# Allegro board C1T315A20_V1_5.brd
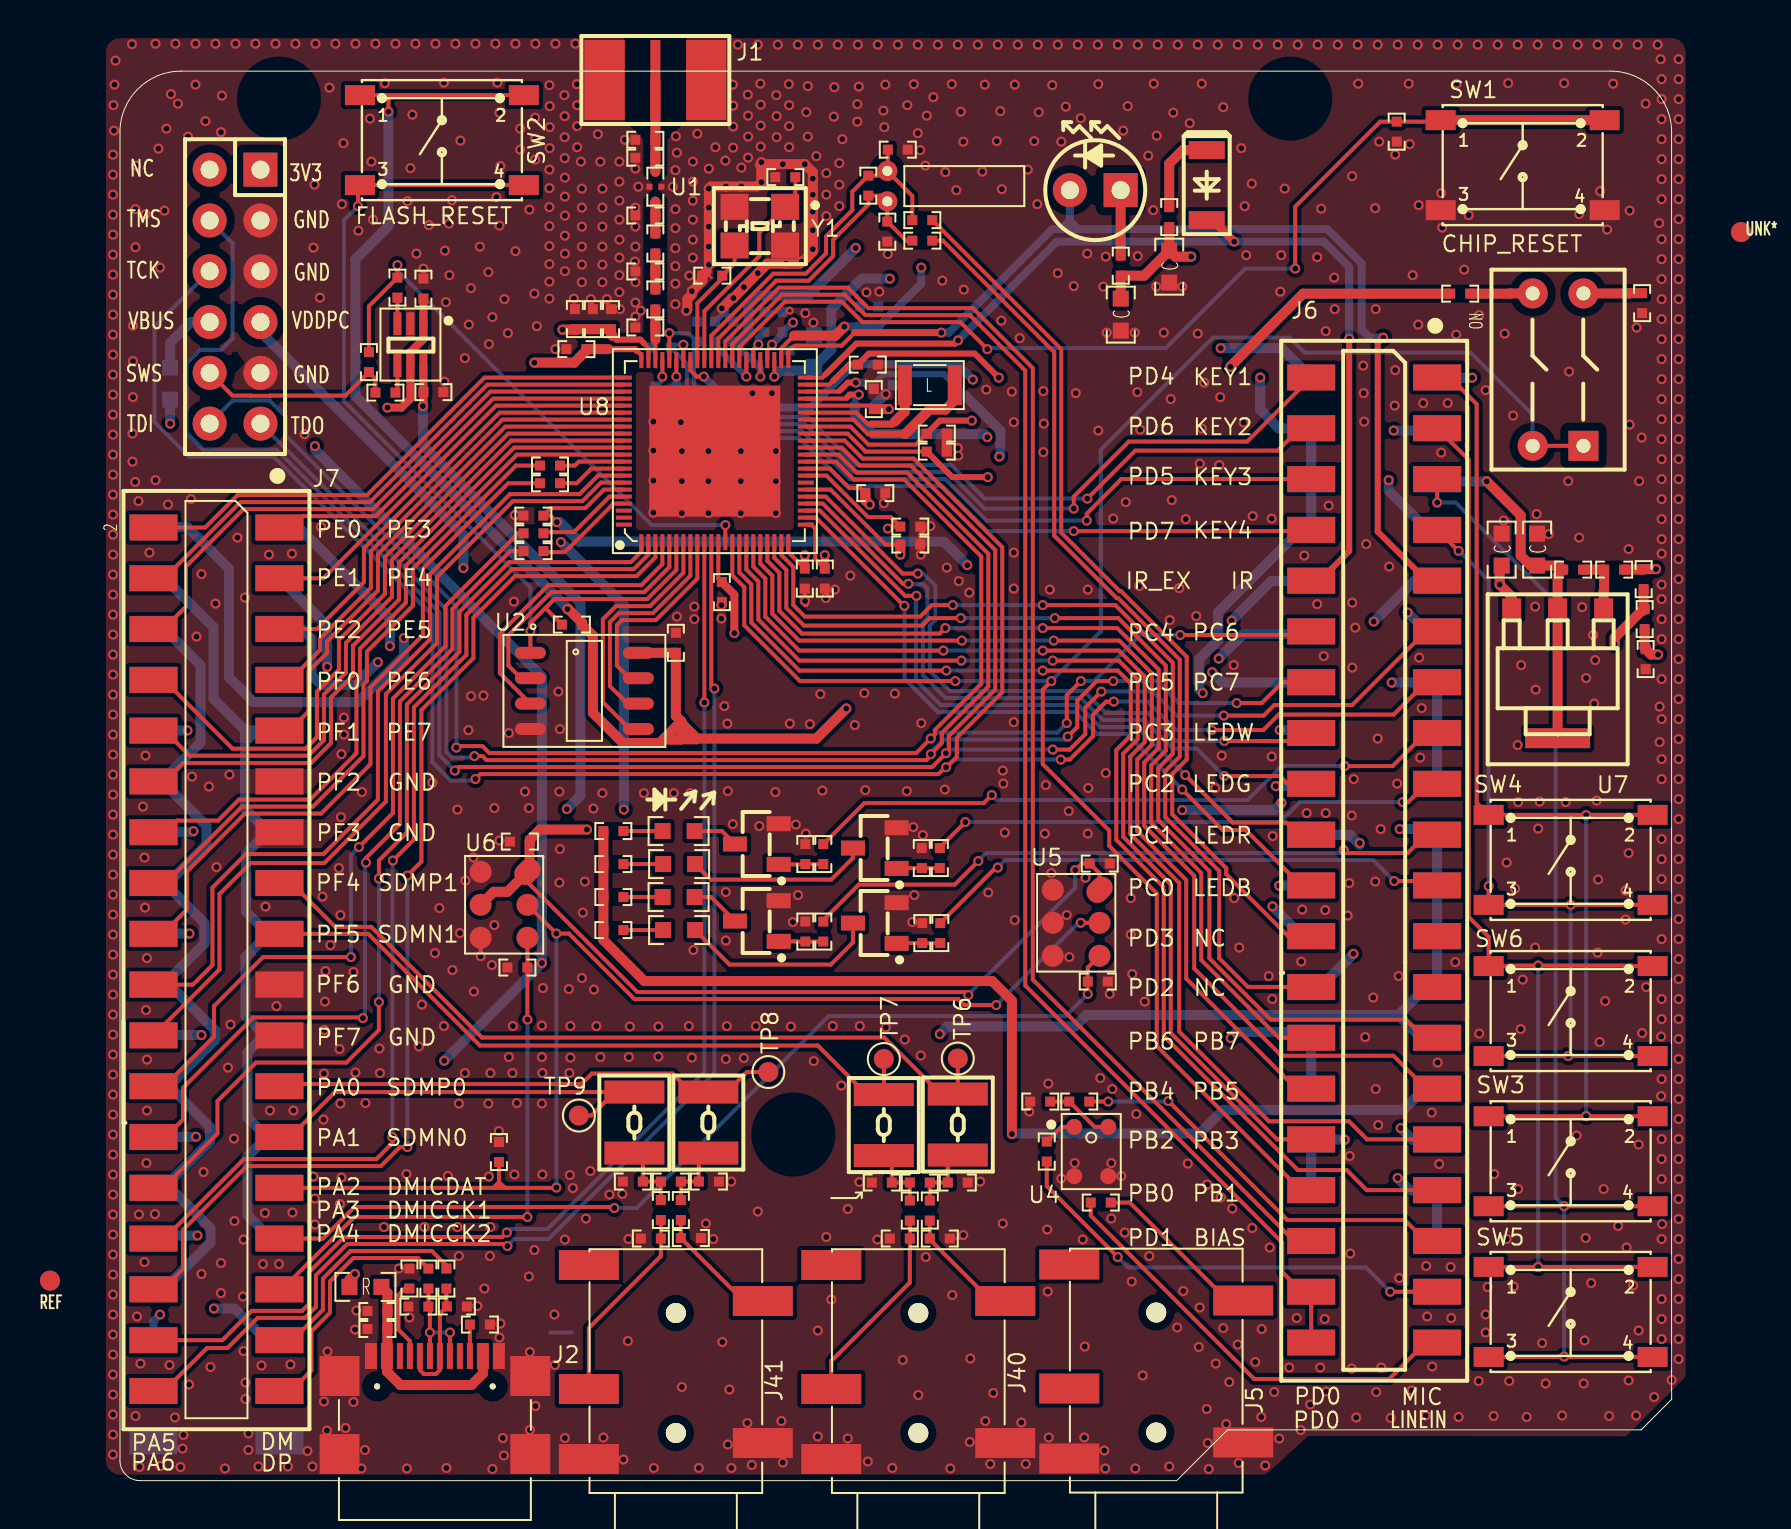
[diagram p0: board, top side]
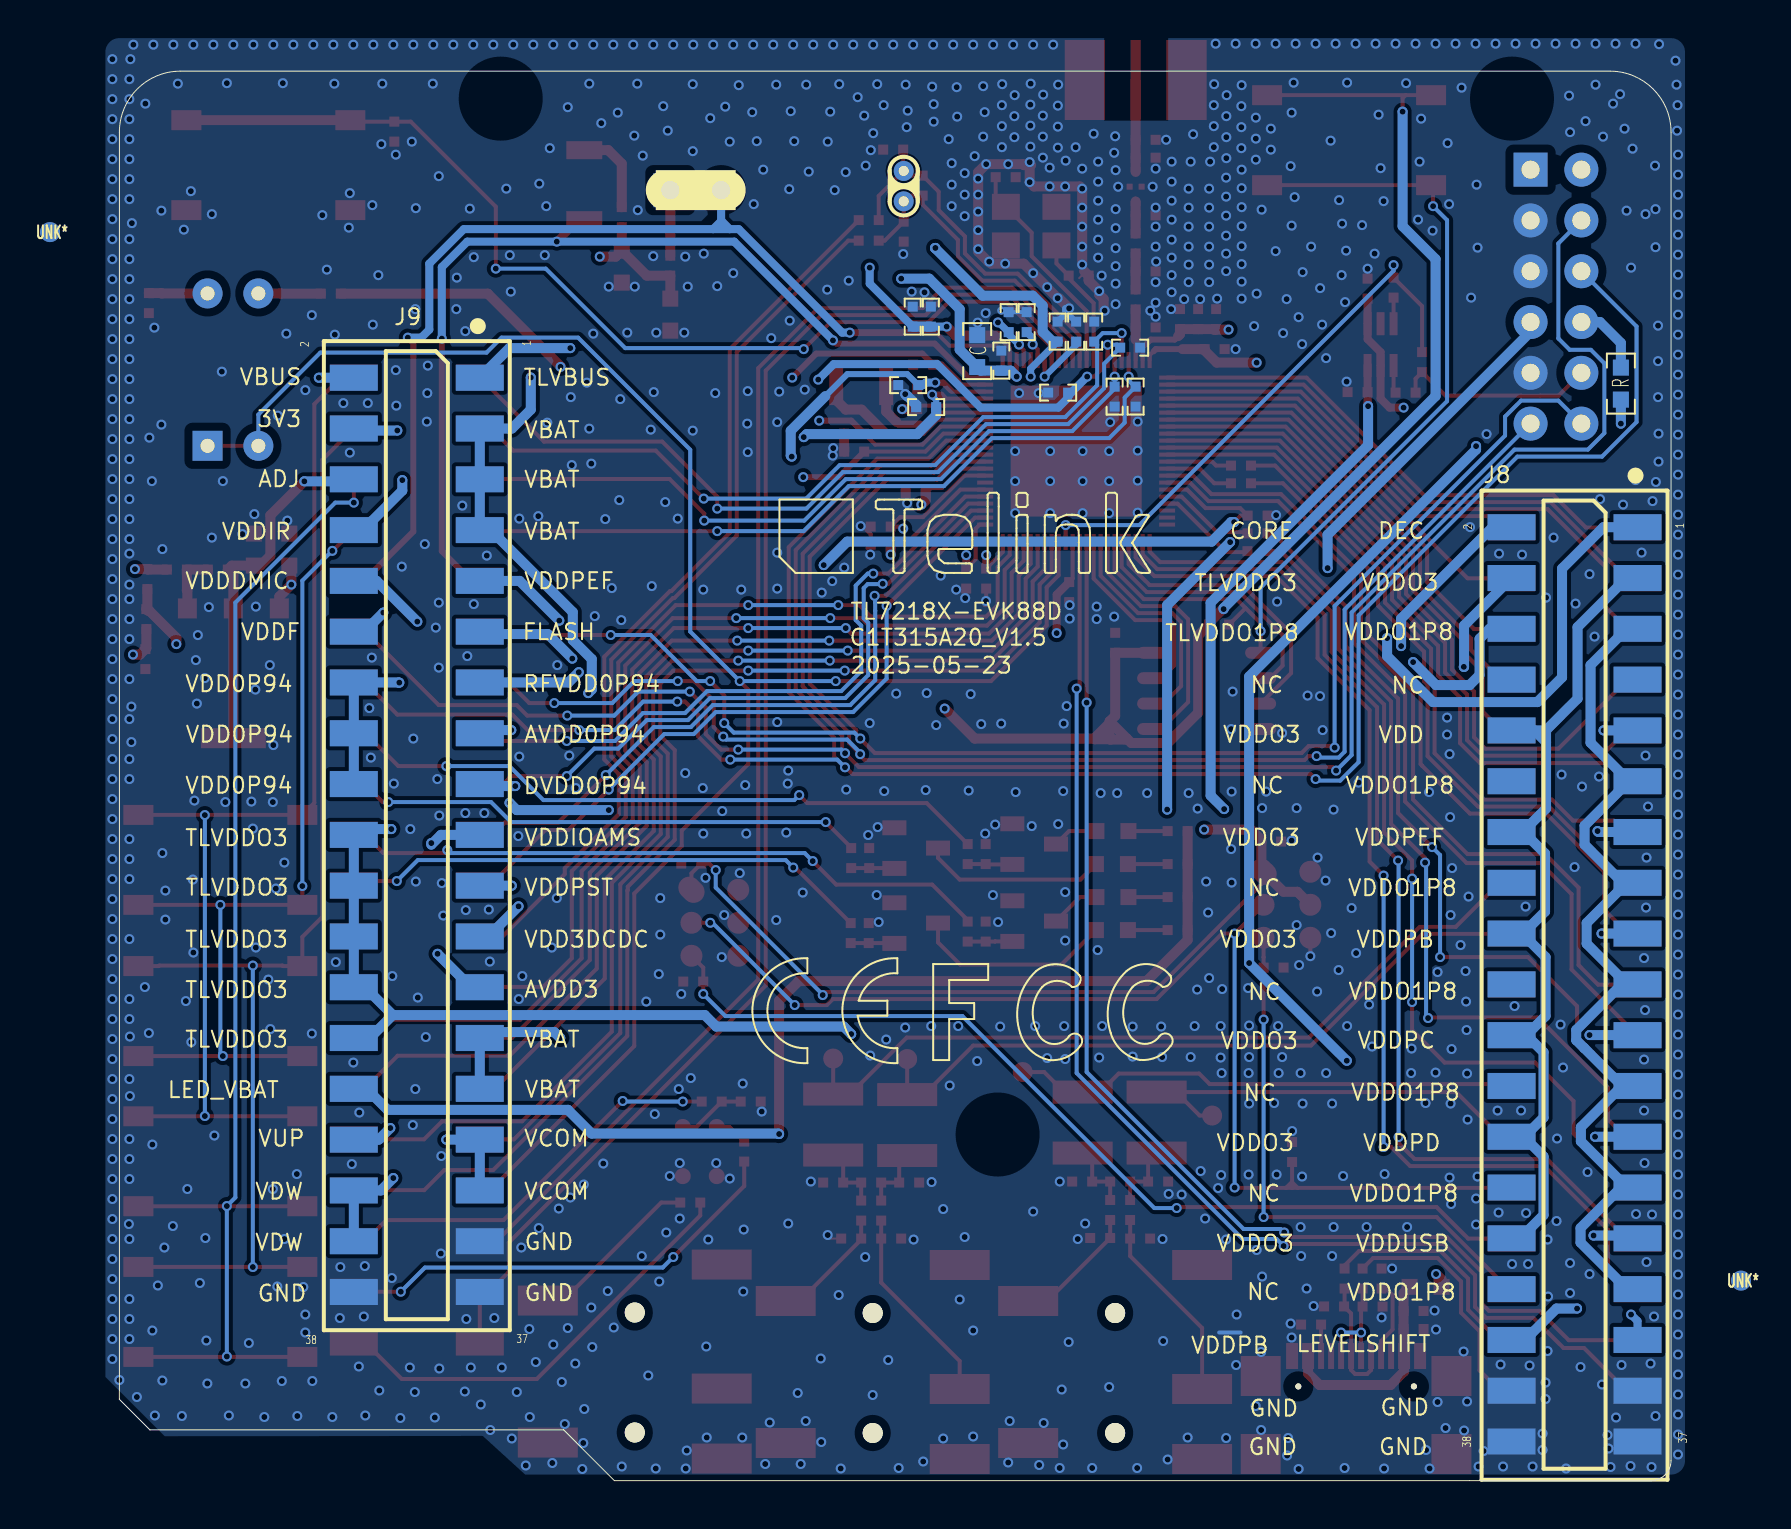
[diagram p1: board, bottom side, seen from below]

Outline 77.6 x 70.48 mm; copper layers: TOP, GND, POWER, BOTTOM. Coordinates in mm from the lower left corner of the outline.
Outline path: 0,67.43 arc(0.89,69.59) 3.05,70.48 74.55,70.48 arc(76.71,69.59) 77.6,67.43 77.6,4.06 76.08,2.54 55.39,2.54 52.85,0 1,0 arc(0.29,0.29) 0,1 0,67.43

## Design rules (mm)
constraint set DEFAULT: min track width 0.1

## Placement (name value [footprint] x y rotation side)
C1  10pF  [0402]  26.77 59.06 90 top
C2  0.5pF  [0402]  26.27 60.46 180 top
C3  3.3pF  [0402]  26.27 63.26 180 top
C4  0.1uF  [0402]  20.68 48.26 180 top
C5  NC  [0402]  29.62 60.26 0 top
C6  NC  [0402]  33.27 65.18 0 top
C7  0.1uF  [0402]  22.82 56.58 0 top
C8  0.1uF  [0402]  23.65 58.08 90 top
C9  4.7uF  [0402]  22.75 58.08 90 top
C10  0.1uF  [0402]  30.65 54.41 180 bottom
C11  1uF  [0402]  63.85 67.45 270 top
C12  0.1uF  [0402]  30.1 44.43 270 top
C13  1uF  [0402]  29.75 57.45 90 bottom
C14  1uF  [0402]  32.23 57.93 90 bottom
C15  1uF  [0402]  30.67 57.45 90 bottom
C17  10uF  [0603C]  34.7 56.48 90 bottom
C18  1uF  [0402]  33.12 57.93 90 bottom
C19  0.1uF  [0402]  34.25 45.1 270 top
C20  1uF  [0402]  37.92 58.2 90 bottom
C21  NC  [0402]  38.38 62.45 90 top
C22  NC  [0402]  38.9 66.56 180 top
C23  0.1uF  [0402]  35.25 45.1 270 top
C24  1uF  [0402]  37.4 55.8 0 top
C25  1uF  [0402]  39.52 46.8 0 top
C26  1uF  [0402]  40.85 51.45 0 top
C27  1uF  [0402]  37.25 53.68 0 bottom
C28  1uF  [0402]  38.15 54.78 0 bottom
C29  1uF  [0402]  39.52 47.7 0 top
C30  1uF  [0402]  37.7 54.08 90 top
C31  1uF  [0402]  37.77 49.38 0 top
C32  1uF  [0402]  40.85 52.35 0 top
C33  1uF  [0402]  27.8 41.89 90 top
C34  0.1uF  [0402]  15.68 54.43 0 top
C35  0.1uF  [0402]  15.18 59.6 90 top
C36  10uF  [0603C]  52.48 60.7 90 top
C37  10uF  [0603C]  50.05 58.3 90 top
C38  10nF  [0402]  46.35 16.45 270 top
C39  1uF  [0402]  46.02 18.95 180 top
C40  10nF  [0402]  49.05 13.9 180 top
C41  0.1uF  [0402]  49 30.86 0 top
C42  0.1uF  [0402]  20 31.95 180 top
C43  10uF  [0603C]  69.1 46.55 90 top
C44  10uF  [0603C]  70.88 46.55 90 top
C45  1.2pF  [0402]  26.27 66.15 180 top
C69  NC  [0402]  38.1 14.91 0 top
C73  220nF  [0402]  40 14.91 0 top
C75  22pF  [0402]  39 12.11 0 top
C76  22pF  [0402]  41 12.11 0 top
C115  NC  [0402]  41.9 14.91 0 top
C116  NC  [0402]  29.45 14.96 0 top
C117  NC  [0402]  25.65 14.96 0 top
C118  22pF  [0402]  26.55 12.11 0 top
C119  22pF  [0402]  28.55 12.13 0 top
C120  220nF  [0402]  27.55 14.96 0 top
C122  1nF  [0402]  18.95 16.43 90 top
C123  3.9pF  [0402]  27.05 56.65 180 bottom
C124  3.9pF  [0402]  27.83 54.2 270 bottom
C125  3.9pF  [0402]  28.85 57.45 90 bottom
C126  3.9pF  [0402]  26.78 54.2 270 bottom
C127  10uF  [0402]  12.88 8.48 0 top
D1  Red  [0603-LED]  27.94 29.18 0 top
D2  White  [0603-LED]  27.94 32.48 0 top
D3  Green  [0603-LED]  27.96 30.83 0 top
D4  Blue  [0603-LED]  27.96 27.53 0 top
D5  LED_IR  [LED_TH_2P54MM_2PIN]  48.77 64.53 0 top
D6  1N4148  [SOD80]  54.35 64.78 270 top
D7  TT0321  [0402]  26.27 57.66 0 top
D8  TT0321  [0402]  26.27 67.05 0 top
D9  ULC0142CDN  [0402]  24.56 58.08 270 top
D10  NC  [0402]  37.02 58.2 270 bottom
D11  ULC0342P10LV  [0402]  33.49 56.01 270 bottom
D12  ESDA05CP30  [0402]  12.88 7.58 0 top
D13  ULC0342P10LV  [0402]  14.93 8.7 180 top
D14  ULC0342P10LV  [0402]  16.85 8.71 0 top
J1  RFIN  [SMA-H]  26.77 70.04 90 top
J2  Type-C 16pin  [TYPE_C_CQ_105PWB]  15.75 5.23 0 top
J3  DIP_2X2  [DIPSWITCH_2P54_7P62_2X2]  71.92 55.55 0 top
J4  JTAG  [HDR254F-2X6X850]  7.03 52.85 90 top
J5  AIL1  [PJ-327]  51.83 -0.6 180 top
J6  HEADER 20x2  [SMD254M-2X20_RX1_30Y2_40]  62.72 28.5 90 top
J7  HEADER 18X2  [SMD254M-2X18_RX1_30Y2_40]  4.82 20.99 90 top
J8  HEADER 19x2  [HDR2X19-2R54-SM-M]  4.82 24.77 90 bottom
J9  HEADER 19x2  [HDR2X19-2R54-SM-M]  62.72 32.25 90 bottom
J40  PJ327  [PJ-327]  39.92 -0.62 180 top
J41  PJ327  [PJ-327]  27.8 -0.62 180 top
L1  2nH  [0402]  26.77 61.86 90 top
L2  6.8uH  [1008L]  40.5 54.78 0 top
L15  150uH  [INDM3025X25]  41.9 17.8 270 top
L16  150uH  [INDM3025X25]  38.2 17.78 270 top
L17  150uH  [INDM3025X25]  29.42 17.91 270 top
L18  150uH  [INDM3025X25]  25.73 17.91 270 top
Q1  C1815  [SOT-23]  31.85 27.98 90 top
Q2  C1815  [SOT-23]  37.75 27.88 90 top
Q3  C1815  [SOT-23]  31.85 31.83 90 top
Q4  C1815  [SOT-23]  37.75 31.63 90 top
R1  NC  [0402]  37.42 64.75 90 top
R3  4.7K  [0402]  22.6 42.8 180 top
R4  33  [0402]  15.43 10.11 90 top
R5  5.1K  [0402]  14.48 10.11 270 top
R6  33  [0402]  16.32 10.11 90 top
R7  1K  [0402]  67.03 59.35 180 top
R8  1M  [0402]  76.12 58.88 270 top
R9  2R  [0603R]  12.28 9.69 0 top
R10  5.1K  [0402]  18 7.8 180 top
R11  0R  [0402]  12.45 55.93 270 top
R12  1K  [0402]  24.68 29.18 0 top
R13  1K  [0402]  24.68 27.53 0 top
R14  1K  [0402]  24.68 32.48 0 top
R15  1K  [0402]  24.68 30.83 0 top
R16  1R  [0402]  50.05 60.76 90 top
R17  0R  [0402]  52.48 63.18 90 top
R18  2.2K  [0402]  47.98 18.95 180 top
R19  1K  [0402]  35.17 27.45 270 top
R20  1K  [0402]  41.02 27.38 270 top
R21  1K  [0402]  35.17 31.33 270 top
R22  1K  [0402]  41 31.13 270 top
R23  10K  [0402]  34.27 27.45 90 top
R24  10K  [0402]  40.12 27.38 90 top
R25  10K  [0402]  34.27 31.33 90 top
R26  10K  [0402]  40.1 31.13 90 top
R27  100K  [0402]  48.9 24.95 180 top
R28  100K  [0402]  19.88 25.66 0 top
R29  430R  [0402]  74.72 45.55 0 top
R30  1.15K  [0402]  76.2 45.08 270 top
R31  787R  [0402]  76.25 43.08 270 top
R32  464R  [0402]  76.3 41.08 270 top
R33  1K  [0402]  72.67 45.55 180 top
R34  0R  [0402]  40.12 62.01 180 top
R35  0R  [0402]  40.12 63.03 180 top
R36  NC  [0402]  13.88 59.66 270 top
R37  NC  [0402]  13.27 54.41 180 top
R38  2R  [0603R]  2.51 54.85 90 bottom
R40  240R  [0402R]  40.5 13.5 270 top
R41  240R  [0402R]  39.5 13.5 270 top
R42  240R  [0402R]  28.05 13.53 270 top
R43  240R  [0402R]  27.05 13.53 270 top
R44  0R  [0402R]  21.51 50.76 0 top
R45  0R  [0402R]  21.51 49.87 0 top
R46  0R  [0402R]  20.68 46.48 0 top
R47  0R  [0402R]  20.68 47.37 0 top
REF  -  [unnamed]  -3.5 10 0 top
SW1  SW4PIN_4.5x4.5  [SW_6X6_SMD]  70.15 65.78 0 top
SW2  FRST  [SW_6X6_SMD]  16.1 67.03 0 top
SW3  SW4PIN_4.5x4.5  [SW_6X6_SMD]  72.55 15.97 0 top
SW4  SW4PIN_4.5x4.5  [SW_6X6_SMD]  72.55 31.04 0 top
SW5  SW4PIN_4.5x4.5  [SW_6X6_SMD]  72.55 8.44 0 top
SW6  SW4PIN_4.5x4.5  [SW_6X6_SMD]  72.55 23.48 0 top
TP6  D5  [TP100]  41.9 21.11 0 top
TP7  D4  [TP100]  38.2 21.08 0 top
TP8  B1  [TP100]  32.42 20.43 270 top
TP9  B0  [TP100]  22.95 18.26 270 top
U1  1.2nH  [BANDPASS]  26.77 64.7 90 top
U2  P25Q16S  [W25X10_20_40BL]  23.23 39.49 270 top
U3  NC/TXS0101  [SC70-6]  14.52 56.8 180 top
U4  WMM7037AT2  [GA_BFA423_A83]  48.58 16.45 0 top
U5  WMM7047DTFN0  [DMIC_SPM0423HM4H-WB]  47.82 27.89 270 top
U6  WMM7047DTFN0  [DMIC_SPM0423HM4H-WB]  19.21 28.79 270 top
U7  LM1117-ADJ  [SOT-223]  71.9 40.12 180 top
U8  TL7218X  [QFN_9X9_88PIN_0P35_6P50X6P50]  29.75 51.48 90 top
UNK*  -  [unnamed]  81.07 62.43 0 top
UNK*#2  -  [unnamed]  81.07 62.43 180 bottom
UNK*#3  -  [unnamed]  -3.5 10 180 bottom
Y1  24MHz-6pF-+/-10ppm  [OSCCC250X320X110]  32 62.73 270 top
Y2  32.768KHz - 9pf - +/-20ppm  [OSC_2X6]  42.38 64.73 180 top

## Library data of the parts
C1-C3 C21 C22 C45 = C1608_NC
C4 C7-C15 C17-C20 C23-C33 C36-C40 C123-C127 = C1005X5R1C104K
C5 C6 C69 C115-C117 = C1005_NC
C34 C35 C44 = C1608X5R1C105M
C41 C42 C122 = C1005X5R1C104K_1
C43 = C1608X5R0J106M
C73 C120 = C1005X5R1C224M
C75 C76 C118 C119 = C1005C0G1H100D
D1-D4 = 0603D_Green
D5 = Led_Th_3mm_1: User Part Number: partnum; Tolerance: RichardLC
D6 = Diode_1N4148
D7 D13 D14 = ESD5B5_2.0ST1G
D8-D12 = ESD5B5_3.0ST1G
J1 = SMA_JACK_2
J2 = Type-C 16pin_0
J3 = HEADER 2X2_0: Tolerance: RichardLC; User Part Number: pn
J4 = HEADER 6X2: Tolerance: RichardLC; User Part Number: pn
J5 J40 J41 = PJ327_2
J6 = HEADER 20x2/M: Tolerance: RichardLC
J7 = HEADER 18X2: Tolerance: RichardLC
J8 J9 = HEADER 19x2: Tolerance: RichardLC
L1 = MLK1608_000R
L2 = IND_0: Tolerance: RichardLC; User Part Number: pn
L15-L18 = IND_150uH_3025
Q1-Q4 = NPN_C1815
R1 R11 = RS0603K102JT
R3 R7 R8 R18 R27 R28 R36 R37 = RS0402K104JT
R4-R6 R9 R10 = RS0402K330JT: room: USB
R12-R17 = RS0402K102JT
R19-R26 R34 R35 = RS0402K101JT
R29-R33 R38 = RS0603K104JT
R40-R43 = RS0402K330JT
R44 R46 R47 = R_7
R45 = R_6
SW1 SW3-SW6 = SW_6X6_SMD_0
SW2 = SW_6X6_SMD
TP6-TP9 = TestPad100
U1 = 4 HEADER_3
U2 = GD25LD40C_0: Tolerance: RichardLC
U3 = TXS0101
U4 = MULPS4CX-RM5_0
U5 U6 = LD1117/SO_0
U7 = XC62FP3302_0.3V_SOT-89
U8 = TL7218X-TLSR9258A-QFN88A: User Part Number: pn; Tolerance: RichardLC
Y1 = CRYSTAL4/SM_0: Tolerance: RichardLC
Y2 = OSC_2x6_2pin_16Mhz

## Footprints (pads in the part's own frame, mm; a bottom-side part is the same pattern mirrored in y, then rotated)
0402
  rect 0.5x0.5 smd: 1(-0.5,0) 2(0.5,0)
0402R
  rect 0.5x0.5 smd: 1(-0.5,0) 2(0.5,0)
0603-LED
  rect 0.8x0.8 smd: A(-0.8,0) C(0.8,0)
0603C
  rect 0.8x0.8 smd: 1(-0.8,0) 2(0.8,0)
0603R
  rect 0.8x0.8 smd: 1(-0.8,0) 2(0.8,0)
1008L
  rect 0.7x2 smd: 1(-1.25,0) 2(1.25,0)
BANDPASS
  rect 0.3x0.3 smd: 1(0,0.3) 3(0,-0.3)
  custom 0.125x0.125 smd: 2(0.74,0) 4(-0.74,0)
DIPSWITCH_2P54_7P62_2X2
  rect 1.5x1.5 hole 0.7: 1(1.27,-3.81)
  round 1.5 hole 0.7: 2(1.27,3.81) 3(-1.27,-3.81) 4(-1.27,3.81)
DMIC_SPM0423HM4H-WB
  round 1.1 smd: 1(-1.65,-1.17) 2(0,-1.17) 3(1.65,-1.17) 4(1.65,1.17) 5(0,1.17)
  oval 1.4x1.1 smd rot 135: 6(-1.65,1.17)
GA_BFA423_A83
  round 0.8 smd: 1(-0.85,1.23) 2(-0.85,-1.23) 3(0.85,-1.23) 4(0.85,1.23)
HDR2X19-2R54-SM-M
  rect 1.3x2.4 smd: 1(22.9,-3.15) 2(22.9,3.15) 3(20.36,-3.15) 4(20.36,3.15) 5(17.82,-3.15) 6(17.82,3.15) 7(15.28,-3.15) 8(15.28,3.15) 9(12.74,-3.15) 10(12.74,3.15) 11(10.2,-3.15) 12(10.2,3.15) 13(7.66,-3.15) 14(7.66,3.15) 15(5.12,-3.15) 16(5.12,3.15) 17(2.58,-3.15) 18(2.58,3.15) 19(0.04,-3.15) 20(0.04,3.15) 21(-2.5,-3.15) 22(-2.5,3.15) 23(-5.04,-3.15) 24(-5.04,3.15) 25(-7.58,-3.15) 26(-7.58,3.15) 27(-10.12,-3.15) 28(-10.12,3.15) 29(-12.66,-3.15) 30(-12.66,3.15) 31(-15.2,-3.15) 32(-15.2,3.15) 33(-17.74,-3.15) 34(-17.74,3.15) 35(-20.28,-3.15) 36(-20.28,3.15) 37(-22.82,-3.15) 38(-22.82,3.15)
HDR254F-2X6X850
  rect 1.7x1.7 hole 0.9: 1(12.7,0)
  round 1.7 hole 0.9: 2(12.7,2.54) 3(10.16,0) 4(10.16,2.54) 5(7.62,0) 6(7.62,2.54) 7(5.08,0) 8(5.08,2.54) 9(2.54,0) 10(2.54,2.54) 11(0,0) 12(0,2.54)
INDM3025X25
  rect 1.15x3 smd: 1(-1.525,0) 2(1.525,0)
LED_TH_2P54MM_2PIN
  rect 1.7x1.7 hole 0.9: A(1.27,0)
  round 1.7 hole 0.9: C(-1.27,0)
OSC_2X6
  round 1 hole 0.5: 1(4,0.76) 2(4,-0.76)
OSCCC250X320X110
  rect 1.3x1.4 smd: 1(-0.965,1.265) 2(-0.965,-1.265) 3(0.965,-1.265) 4(0.965,1.265)
PJ-327
  round 1 hole 1 unplated: (0,-3) (0,-9)
  rect 3x1.5 smd: 1(-4.35,-2.5) 2(4.35,-5.2) 3(-4.35,-9.6) 4(4.35,-11.4) 5(4.35,-1.7)
QFN_9X9_88PIN_0P35_6P50X6P50
  rect 0.8x0.2 smd: 1(-4.55,3.675) 2(-4.55,3.325) 3(-4.55,2.975) 4(-4.55,2.625) 5(-4.55,2.275) 6(-4.55,1.925) 7(-4.55,1.575) 8(-4.55,1.225) 9(-4.55,0.875) 10(-4.55,0.525) 11(-4.55,0.175) 12(-4.55,-0.175) 13(-4.55,-0.525) 14(-4.55,-0.875) 15(-4.55,-1.225) 16(-4.55,-1.575) 17(-4.55,-1.925) 18(-4.55,-2.275) 19(-4.55,-2.625) 20(-4.55,-2.975) 21(-4.55,-3.325) 22(-4.55,-3.675) 45(4.55,-3.675) 46(4.55,-3.325) 47(4.55,-2.975) 48(4.55,-2.625) 49(4.55,-2.275) 50(4.55,-1.925) 51(4.55,-1.575) 52(4.55,-1.225) 53(4.55,-0.875) 54(4.55,-0.525) 55(4.55,-0.175) 56(4.55,0.175) 57(4.55,0.525) 58(4.55,0.875) 59(4.55,1.225) 60(4.55,1.575) 61(4.55,1.925) 62(4.55,2.275) 63(4.55,2.625) 64(4.55,2.975) 65(4.55,3.325) 66(4.55,3.675)
  rect 0.2x0.8 smd: 23(-3.675,-4.55) 24(-3.325,-4.55) 25(-2.975,-4.55) 26(-2.625,-4.55) 27(-2.275,-4.55) 28(-1.925,-4.55) 29(-1.575,-4.55) 30(-1.225,-4.55) 31(-0.875,-4.55) 32(-0.525,-4.55) 33(-0.175,-4.55) 34(0.175,-4.55) 35(0.525,-4.55) 36(0.875,-4.55) 37(1.225,-4.55) 38(1.575,-4.55) 39(1.925,-4.55) 40(2.275,-4.55) 41(2.625,-4.55) 42(2.975,-4.55) 43(3.325,-4.55) 44(3.675,-4.55) 67(3.675,4.55) 68(3.325,4.55) 69(2.975,4.55) 70(2.625,4.55) 71(2.275,4.55) 72(1.925,4.55) 73(1.575,4.55) 74(1.225,4.55) 75(0.875,4.55) 76(0.525,4.55) 77(0.175,4.55) 78(-0.175,4.55) 79(-0.525,4.55) 80(-0.875,4.55) 81(-1.225,4.55) 82(-1.575,4.55) 83(-1.925,4.55) 84(-2.275,4.55) 85(-2.625,4.55) 86(-2.975,4.55) 87(-3.325,4.55) 88(-3.675,4.55)
  rect 6.55x6.55 smd: 89(0,0)
SC70-6
  rect 0.4x1.15 smd: 1(-0.65,-1.045) 2(0,-1.045) 3(0.65,-1.045) 4(0.65,1.045) 5(0,1.045) 6(-0.65,1.045)
SMA-H
  rect 4x0.5 smd: 1(0,0)
  rect 4x2 smd: 2(0,-2.54) 3(0,2.54) 4(0,-2.54) 5(0,2.54)
SMD254M-2X18_RX1_30Y2_40
  rect 1.3x2.4 smd: 1(26.67,-3.15) 2(26.67,3.15) 3(24.13,-3.15) 4(24.13,3.15) 5(21.59,-3.15) 6(21.59,3.15) 7(19.05,-3.15) 8(19.05,3.15) 9(16.51,-3.15) 10(16.51,3.15) 11(13.97,-3.15) 12(13.97,3.15) 13(11.43,-3.15) 14(11.43,3.15) 15(8.89,-3.15) 16(8.89,3.15) 17(6.35,-3.15) 18(6.35,3.15) 19(3.81,-3.15) 20(3.81,3.15) 21(1.27,-3.15) 22(1.27,3.15) 23(-1.27,-3.15) 24(-1.27,3.15) 25(-3.81,-3.15) 26(-3.81,3.15) 27(-6.35,-3.15) 28(-6.35,3.15) 29(-8.89,-3.15) 30(-8.89,3.15) 31(-11.43,-3.15) 32(-11.43,3.15) 33(-13.97,-3.15) 34(-13.97,3.15) 35(-16.51,-3.15) 36(-16.51,3.15)
SMD254M-2X20_RX1_30Y2_40
  rect 1.3x2.4 smd: 1(26.67,-3.15) 2(26.67,3.15) 3(24.13,-3.15) 4(24.13,3.15) 5(21.59,-3.15) 6(21.59,3.15) 7(19.05,-3.15) 8(19.05,3.15) 9(16.51,-3.15) 10(16.51,3.15) 11(13.97,-3.15) 12(13.97,3.15) 13(11.43,-3.15) 14(11.43,3.15) 15(8.89,-3.15) 16(8.89,3.15) 17(6.35,-3.15) 18(6.35,3.15) 19(3.81,-3.15) 20(3.81,3.15) 21(1.27,-3.15) 22(1.27,3.15) 23(-1.27,-3.15) 24(-1.27,3.15) 25(-3.81,-3.15) 26(-3.81,3.15) 27(-6.35,-3.15) 28(-6.35,3.15) 29(-8.89,-3.15) 30(-8.89,3.15) 31(-11.43,-3.15) 32(-11.43,3.15) 33(-13.97,-3.15) 34(-13.97,3.15) 35(-16.51,-3.15) 36(-16.51,3.15) 37(-19.05,-3.15) 38(-19.05,3.15) 39(-21.59,-3.15) 40(-21.59,3.15)
SOD80
  rect 0.9x1.8 smd: A(-1.75,0) C(1.75,0)
SOT-23
  rect 0.75x1.2 smd: 1(-1.016,-1.092) 2(1.016,-1.092) 3(0,1.092)
SOT-223
  rect 0.95x1 smd: 1(-2.3,-3.495) 2(0,-3.495) 3(2.3,-3.495)
  rect 3.25x1 smd: 4(0,2.995)
SW_6X6_SMD
  rect 1.5x1 smd: 1(-4.1,2.25) 2(4.1,2.25) 3(-4.1,-2.25) 4(4.1,-2.25)
TP100
  round 1 smd: 1(0,0)
TYPE_C_CQ_105PWB
  round 0.3 hole 0.7 unplated: (-2.89,-0.52) (2.89,-0.52)
  rect 2x2 smd: 13(-4.77,0) 14(4.77,0) 15(-4.77,-3.9) 16(4.77,-3.9)
  rect 0.6x1.3 smd: A1B12(-3.2,1) A4B9(-2.4,1) B1A12(3.2,1) B4A9(2.4,1)
  rect 0.3x1.3 smd: A5(-1.25,1) A6(-0.25,1) A7(0.25,1) A8(1.25,1) B5(1.75,1) B6(0.75,1) B7(-0.75,1) B8(-1.75,1)
unnamed
  round 1 smd: 1(0,0)
W25X10_20_40BL
  oval 0.6x1.55 smd: 1(-1.905,-2.7) 2(-0.635,-2.7) 3(0.635,-2.7) 4(1.905,-2.7) 5(1.905,2.7) 6(0.635,2.7) 7(-0.635,2.7) 8(-1.905,2.7)

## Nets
GND: C2.2 C3.2 C4.2 C5.1 C6.1 C7.1 C8.2 C9.2 C10.1 C11.2 C12.2 C13.2 C14.2 C15.2 C17.2 C18.2 C19.2 C20.2 C21.1 C22.1 C23.2 C24.2 C25.2 C26.2 C27.2 C28.2 C29.2 C30.2 C31.2 C32.2 C33.2 C34.2 C35.2 C36.1 C37.1 C39.2 C41.2 C42.2 C43.2 C44.2 C45.2 C69.1 C75.1 C76.2 C115.2 C116.2 C117.1 C118.1 C119.2 C122.2 C123.2 C124.2 C125.2 C126.2 C127.1 D7.1 D8.1 D9.1 D10.1 D11.1 D12.1 D13.2 D14.2 J1.2 J1.3 J1.4 J1.5 J2.13 J2.14 J2.15 J2.16 J2.A1B12 J2.B1A12 J4.3 J4.5 J4.9 J5.1 J5.5 J7.11 J7.13 J7.19 J7.21 J8.35 J8.36 J8.37 J8.38 J9.35 J9.37 J9.38 J40.1 J40.5 J41.1 J41.5 Q1.2(E) Q2.2(E) Q3.2(E) Q4.2(E) R5.1 R8.2 R10.1 R23.2 R24.2 R25.2 R26.2 R27.1 R28.1 R32.2 SW1.3 SW1.4 U1.1 U1.3 U2.4 U3.2 U4.2 U4.3 U5.1 U5.2(SE) U5.3 U6.1 U6.3 U8.89 Y1.2 Y1.4
VBAT_ADJ: C44.1 J9.6 R33.2 U7.2 U7.4(VOUT#4)
VBUS: C43.1 J9.2 R9.1 R38.1 U7.3
VDDO1P8: J8.5 J8.11 J8.15 J8.19 J8.23 J8.27 J8.31
VDDO3: J8.3 J8.10 J8.14 J8.18 J8.22 J8.26 J8.30
AIN_LINEIN: C40.2 J6.39
AIN_MIC: C38.2 J6.37
BEVK_SWS: J4.10 R11.2 R37.2
DM: D14.1 J2.A7 J2.B7 R6.1
DMICCK1: J7.29 R27.2 U5.4
DMICCK2: J7.31 R28.2 U6.4
DMICDAT: C122.1 J7.27 U5.5 U6.5
DP: D13.1 J2.A6 J2.B6 R4.1
EXT_3V3: C34.1 J4.1 J9.4 U3.6(VCCB)
LED_B: J6.21 R20.1
LED_G: J6.17 R22.1
LED_R: J6.19 R19.1
LED_VBAT: J9.30 R12.1 R13.1 R14.1 R15.1
LED_W: J6.15 R21.1
LEVEL_SHIFT: C35.1 J8.33 U3.1 U3.5
MICBIAS: J6.35 R18.1
TL_ANT: C1.1 D7.2 U8.64
TL_AVDD0P94: C28.1 J9.15 U8.42
TL_AVDD3: C15.1 J9.25 U8.49
TL_DM: J7.33 R6.2
TL_DP: J7.35 R4.2
TL_DVDD0P94: C27.1 J9.17 U8.41
TL_FLASH: C33.1 J9.11 R3.1 SW2.1 SW2.2 U2.8
TL_IR: D5.C(CATHODE) J6.9 U8.45
TL_IR_EX_DIOD: D6.C J6.10 U8.44
TL_KEY1: J6.1 SW3.1 SW3.2 SW4.1 SW4.2
TL_KEY2: J6.3 SW5.1 SW5.2 SW6.1 SW6.2
TL_KEY3: J6.5 SW3.3 SW3.4 SW5.3 SW5.4
TL_KEY4: J6.7 SW4.3 SW4.4 SW6.3 SW6.4
TL_PA0: J7.24 R47.1
TL_PA0_SDMP0: J7.23 L17.1 TP8.1(TP)
TL_PA1: J7.26 R46.1
TL_PA1_SDMN0: J7.25 L18.1 TP9.1(TP)
TL_PA2: J7.28 U8.1
TL_PA3: J7.30 U8.2
TL_PA4: J7.32 U8.3
TL_PA5_DM: J7.34 U8.10
TL_PA6_DP: J7.36 U8.11
TL_PA7_SWS: R11.1 R36.1 U8.13
TL_PB0: J3.1 J3.3 J6.34 U8.14
TL_PB1: J6.33 U8.15
TL_PB2: J6.32 U8.16
TL_PB3: J6.31 U8.17
TL_PB4: J6.30 U8.18
TL_PB5: J6.29 U8.19
TL_PB6: J6.28 U8.20
TL_PB7: J6.27 U8.21
TL_PC0: J6.22 U8.24
TL_PC1: J6.20 U8.25
TL_PC2: J6.18 U8.26
TL_PC3: J6.16 U8.27
TL_PC4_TDI: J4.12 J6.12 U8.32
TL_PC5_TDO: J4.11 J6.14 U8.33
TL_PC6_TMS: J4.4 J6.11 U8.34
TL_PC7_TCK: J4.6 J6.13 U8.35
TL_PD0_AMIC: J6.38 J6.40 U8.53
TL_PD1_MICBIAS: J6.36 U8.54
TL_PD2_32K: C21.2 R1.1 R34.2 U8.55 Y2.1
TL_PD2_NC_32K: J6.26 R34.1
TL_PD3_32K: C22.2 R1.2 R35.2 U8.56 Y2.2
TL_PD3_NC_32K: J6.24 R35.1
TL_PD4: C123.1 J6.2 U8.60
TL_PD5: C124.1 J6.6 U8.61
TL_PD6: C125.1 J6.4 U8.62
TL_PD7: C126.1 J6.8 U8.63
TL_PE0: J7.2 U8.67
TL_PE1: J7.4 U8.68
TL_PE2: J7.6 U8.69
TL_PE3: J7.1 U8.70
TL_PE4: J7.3 U8.71
TL_PE5: J7.5 U8.72
TL_PE6: J7.7 U8.73
TL_PE7: J7.9 U8.74
TL_PF0: J7.8 U8.75
TL_PF1: J7.10 U8.76
TL_PF2: J7.12 U8.77
TL_PF3: J7.14 U8.78
TL_PF4: J7.16 R44.1
TL_PF4_SDMP1: J7.15 L15.1 TP6.1(TP)
TL_PF5: J7.18 R45.1
TL_PF5_SDMN1: J7.17 L16.1 TP7.1(TP)
TL_PF6: J7.20 U8.81
TL_PF7: J7.22 U8.82
TL_PG0_MOSI: U2.5 U8.7
TL_PG1_MCLK: U2.6 U8.8
TL_PG2_MSIO3: U2.7 U8.9
TL_PG3_MSCN: R3.2 SW2.3 SW2.4 U2.1 U8.6
TL_PG4_MISO: U2.2 U8.5
TL_PG5_MSIO2: U2.3(W\P\/IO2) U8.4
TL_RFVDD_0P94: C8.1 C9.1 D9.2 J9.13 U8.65
TL_VBAT: C17.1 D11.2 J9.3 J9.5 J9.7 J9.27 J9.29 U8.47
TL_VBUS: C20.1 D10.2 J9.1 U8.46
TL_VDD: C7.2 J8.9 U8.66
TL_VDD0P94: C30.1 J9.14 J9.16 J9.18 U8.40
TL_VDD3DCDC: C32.1 J9.23 U8.37
TL_VDD_DMIC: C41.1 C42.1 J9.10 U5.6 U6.2(SE) U6.6
TL_VDD_F: C24.1 J9.12 U8.43
TL_VDD_IR: C36.2 C37.2 J9.8 R16.1 R17.1
TL_VDDCORE: C29.1 J8.2 U8.30
TL_VDDDEC: C31.1 J8.1 U8.31
TL_VDDIO_AMS: C14.1 J9.19 U8.50
TL_VDDIO_PB: C19.1 J8.17 J8.34 U8.22
TL_VDDIO_PC: C23.1 J4.7 J8.21 U8.23
TL_VDDIO_PD: C10.2 J8.25 U8.59
TL_VDDIO_PEF: C4.1 J8.13 J9.9 U8.83
TL_VDDIO_USB: C12.1 J8.29 U8.12
TL_VDDO1P8: C25.1 J8.6 U8.28
TL_VDDO3: C18.1 J8.4 J9.20 J9.22 J9.24 J9.26 J9.28 R7.2 U8.48
TL_VDDPST: C26.1 J9.21 U8.36
TL_XC1: C5.2 U8.58 Y1.3
TL_XC2: C6.2 U8.57(XC2) Y1.1
USB_VBUS: C127.2 D12.2 J2.A4B9 J2.B4A9(VBUS#B4A9) R9.2
VCOM: J9.31 J9.33 R30.2 R31.1
VDW: J9.34 J9.36 R31.2 R32.1
VUP: J9.32 R29.2 R30.1
N20028206: R29.1 R33.1 U7.1
N20230476: Q1.1 R19.2 R23.1
N20230490: Q2.1 R20.2 R24.1
N20230526: Q3.1 R21.2 R25.1
N20230570: Q4.1 R22.2 R26.1
N20230742: D1.A R12.2
N20230744: D1.C(CATHODE) Q1.3
N20230746: D4.A R13.2
N20230748: D4.C(CATHODE) Q2.3
N20230750: D2.A R14.2
N20230752: D2.C(CATHODE) Q3.3
N20230754: D3.A R15.2
N20230756: D3.C(CATHODE) Q4.3
N20248227: C39.1 R18.2 U4.4(VDD)
N20254983: C38.1 U4.1
N20255175: C40.1 J5.3
N20271178: D5.A R16.2
N20271193: D6.A R17.2
N20286198: R45.2 U8.80
N20286201: R44.2 U8.79
N20286912: C11.1 SW1.1 SW1.2 U8.52
N20286959: C13.1 U8.51
N20290975: L2.2 U8.38
N20290977: L2.1 U8.39
N20305837: J2.A5 R5.2
N20305839: J2.B5 R10.2
N20310970: C1.2 C2.1 L1.1
N20310976: C3.1 L1.2 U1.4
N20348750: J4.8 R38.2
N20353968: C69.2 C73.1 L16.2 R41.1
N20353978: C75.2 J40.2 R41.2
N20354017: C73.2 C115.1 L15.2 R40.1
N20354025: C76.1 J40.3 R40.2
N20354127: C117.2 C120.1 L18.2 R43.1
N20354137: C118.2 J41.2 R43.2
N20354176: C116.1 C120.2 L17.2 R42.1
N20354184: C119.1 J41.3 R42.2
N20364573: C45.1 D8.2 J1.1 U1.2
N20368232: R36.2 U3.3
N20378065: R47.2 U8.84
N20378070: R46.2 U8.85
N202243015: R37.1 U3.4
N202309440: J3.2 R8.1
N202309690: J3.4 R7.1

Pads without a net: J2 A8 B8; J4 2; J5 2 4; J6 23 25; J8 7 8 12 16 20 24 28 32; J40 4; J41 4; REF 1; U8 29 86 87 88; UNK* 1; UNK*#2 1; UNK*#3 1

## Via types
v1: diameter 0.5, hole 0.3, TOP to BOTTOM, 1355 vias
v2: diameter 0.4, hole 0.2, TOP to BOTTOM, 1 via

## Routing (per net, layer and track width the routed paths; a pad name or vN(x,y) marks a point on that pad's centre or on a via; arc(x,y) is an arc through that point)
GND: length 34
  TOP w0.1: v1(71.45,47.33) 71.35,47.33 71.33,47.35 C44.2 ; C76.2 42,12.11 v1(42.17,12.28) ; C5.1 29.48,60.26 29.6,60.13
  TOP w0.2: U6.3 v1(18.04,26.22) ; C19.2 34.25,44.13 34.33,44.05 34.33,43.78 34.26,43.78 v1(34.26,43.98) ; C25.2 40.02,47.32 40.23,47.53 ; v1(32.8,49.98) 32.88,49.91 ; C31.2 38.2,49.31 v1(38.2,48.88)
  TOP w0.5: C32.2 C26.2 ; v1(30.1,58.62) 30.61,59.13 v1(30.67,59.13) 31.2,59.66 v1(31.2,59.68) v1(31.9,60.38) 32.38,60.85 v1(33.3,60.85) 34,60.85 v1(34.1,60.95) 34.15,60.95 34.65,61.45 v1(34.65,61.58) v1(34.65,62.53) v1(34.65,63.45) v1(34.65,64.31) v1(34.65,65.1) 34.65,65.43 v1(34.25,65.83) v1(33.15,65.83) 32.4,65.83 32.35,65.78 32,65.78 ; v1(29.45,60.8) v1(29.45,61.7) v1(29.45,62.7) v1(29.45,63.66) v1(29.45,64.6) 29.56,64.72 v1(30.3,64.72) v1(31.08,64.72) 31.86,64.72 v1(32.08,64.93) v1(32.08,65.93) ; 29.35,60.48 C5.1 29.12,60.01 v1(28.6,59.48) 28.6,59.31 28.38,59.09 28.38,58.55 v1(28.32,58.51)
  GND w0.3: 34.23,60.85 34.2,60.85
  POWER w0.3: 38.48,59.13 38.36,59.02 38.3,59.02
  POWER w0.5: 21.1,33.28 21.07,33.25
  BOTTOM w0.2: 33.2,58.51 C18.2 C14.2 ; v1(34.27,58.38) 34.15,58.51 ; 21.52,7.4 22.6,7.4
  BOTTOM w0.3: 30.23,58.43 30.23,58.41 C15.2 ; 30.23,58.43 30.23,58.43 30.3,58.51 30.3,58.62 v1(30.1,58.62) ; 30.23,58.43 30.17,58.38 30.17,58.35 29.77,57.95 C13.2
  BOTTOM w0.5: C27.2 37.75,53.8 38.18,54.23 38.2,54.23 v1(38.3,54.33)
  vias: v1(-0.35,66.31) v1(-0.35,65.31) v1(-0.35,64.31) v1(-0.35,63.3) v1(-0.35,62.3) v1(-0.35,61.3) v1(-0.35,60.3) v1(-0.35,59.3) v1(-0.35,58.3) v1(-0.35,57.3) v1(-0.35,56.3) v1(-0.35,55.3) v1(-0.35,54.3) v1(-0.35,53.3) v1(-0.35,52.3) v1(-0.35,51.3) v1(-0.35,50.3) v1(-0.35,49.3) v1(-0.35,48.3) v1(-0.35,47.3) v1(-0.35,46.3) v1(-0.35,45.3) v1(-0.35,44.3) v1(-0.35,43.3) v1(-0.35,42.3) v1(-0.35,41.3) v1(-0.35,40.3) v1(-0.35,39.3) v1(-0.35,38.3) v1(-0.35,37.3) v1(-0.35,36.3) v1(-0.35,35.3) v1(-0.35,34.3) v1(-0.35,33.3) v1(-0.35,32.3) v1(-0.35,31.3) v1(-0.35,30.3) v1(-0.35,29.3) v1(-0.35,28.3) v1(-0.35,27.3) v1(-0.35,26.3) v1(-0.35,25.3) v1(-0.35,24.3) v1(-0.35,23.3) v1(-0.35,22.3) v1(-0.35,21.3) v1(-0.35,20.3) v1(-0.35,19.3) v1(-0.35,18.3) v1(-0.35,17.3) v1(-0.35,16.3) v1(-0.35,15.3) v1(-0.35,14.3) v1(-0.35,13.3) v1(-0.35,12.3) v1(-0.35,11.3) v1(-0.35,10.3) v1(-0.35,9.3) v1(-0.35,8.3) v1(-0.35,7.3) v1(-0.35,6.3) v1(-0.35,5.3) v1(-0.35,4.3) v1(-0.35,3.3) v1(-0.35,2.3) v1(-0.35,1.3) v1(-0.27,69.81) v1(-0.33,68.78) v1(-0.3,67.5) v1(-0.23,71) v1(0.6,71.83) v1(0.62,52.35) v1(0.62,50.95) v1(0.65,57.76) v1(0.65,55.98) v1(0.65,54.18) v1(0.8,65.75) v1(0.78,63.58) v1(0.78,61.68) v1(0.76,49.94) v1(0.85,8.21) v1(0.78,3.23) v1(0.92,48.98) v1(0.95,13.3) v1(1.03,5.86) v1(0.97,0.68) v1(1.15,33.7) v1(1.22,31.16) v1(1.22,10.93) v1(1.28,63.33) v1(1.28,36.25) v1(1.25,28.66) v1(1.35,26.13) v1(1.3,23.53) v1(1.35,21.05) v1(1.35,18.51) v1(1.33,15.88) v1(1.47,46.41) v1(1.75,13.33) v1(1.78,71.85) v1(1.78,50.03) v1(1.92,66.6) v1(2,60.66) v1(2.03,0.73) v1(2.22,63.51) v1(2.33,67.6) v1(2.4,48.8) v1(2.55,69.33) v1(2.47,5.78) v1(2.75,3.16) v1(2.78,71.85) v1(2.9,68.85) v1(3.03,0.68) v1(3.12,1.61) v1(3.17,2.28) v1(3.4,67.2) v1(3.55,49.08) v1(3.45,4.8) v1(3.6,35.2) v1(3.78,71.85) v1(3.78,69.81) v1(3.83,42.2) v1(4.08,45.33) v1(4.08,10.33) v1(4.17,15.43) v1(4.28,67.98) v1(4.45,34.7) v1(4.53,5.68) v1(4.78,71.85) v1(4.78,43.85) v1(4.82,30.68) v1(5.1,69.25) v1(5.05,67.43) v1(5.05,10.88) v1(5.05,9.38) v1(5.25,0.61) v1(5.4,20.66) v1(5.47,35.3) v1(5.53,22.8) v1(5.7,17.11) v1(5.72,12.98) v1(5.78,71.85) v1(5.88,47.16) v1(6.18,12.05) v1(6.15,9.21) v1(6.18,6.48) v1(6.25,44.16) v1(6.28,4.91) v1(6.28,4.08) v1(6.43,2.36) v1(6.43,1.53) v1(6.78,71.85) v1(6.93,0.71) v1(7.07,5.75) v1(7.15,10.83) v1(7.28,28.7) v1(7.25,13.38) v1(7.45,46.3) v1(7.5,18.51) v1(7.78,71.85) v1(7.82,23.73) v1(7.95,10.83) v1(8.4,0.71) v1(8.53,5.8) v1(8.6,46.35) v1(8.62,13.4) v1(8.68,18.51) v1(8.78,71.85) v1(9.22,52.33) v1(9.38,1.48) v1(9.62,0.71) v1(9.72,64.81) v1(9.68,61.66) v1(9.68,15.21) v1(9.75,14.11) v1(9.75,12.8) v1(9.78,71.85) v1(10,59.16) v1(10.05,47.68) v1(10.12,29.2) v1(10.22,22.53) v1(10.2,20.36) v1(10.18,18.05) v1(10.2,3.96) v1(10.28,25.48) v1(10.25,23.95) v1(10.35,2.5) v1(10.38,6.46) v1(10.47,69.66) v1(10.53,26.78) v1(10.78,71.85) v1(10.95,30.63) v1(11.03,28.28) v1(10.97,21.58) v1(11.03,18.86) v1(11,13.83) v1(11.1,63.83) v1(11.07,36.33) v1(11.05,33.18) v1(11.07,15.16) v1(11.18,66.88) v1(11.2,38.16) v1(11.2,37.3) v1(11.28,2.63) v1(11.68,25.43) v1(11.68,3.93) v1(11.78,71.85) v1(11.78,20.41) v1(11.82,8.5) v1(11.76,7.55) v1(11.93,62.51) v1(12.1,34.43) v1(12.07,0.61) v1(12.28,18.88) v1(12.25,1.53) v1(12.5,68.1) v1(12.57,65.95) v1(12.65,63.05) v1(12.77,71.85) v1(12.98,21.61) v1(13,20.38) v1(13.2,12.68) v1(13.25,69.88) v1(13.77,71.85) v1(13.95,10.61) v1(14.32,15.33) v1(14.38,63.98) v1(14.35,0.61) v1(14.52,65.63) v1(14.48,8.16) v1(14.62,68.31) v1(14.77,71.85) v1(14.82,61.35) v1(14.95,21.7) v1(15.1,23.8) v1(15.18,60.6) v1(15.23,12.68) v1(15.45,62.78) v1(15.62,34.91) v1(15.75,26.38) v1(15.77,71.85) v1(15.98,28.63) v1(16.2,69.91) v1(16.23,54.95) v1(16.2,22.73) v1(16.25,61.51) v1(16.3,58.93) v1(16.32,0.63) v1(16.45,62.85) v1(16.4,15.23) v1(16.48,60.28) v1(16.6,64.03) v1(16.62,25.53) v1(16.77,71.85) v1(16.88,33.55) v1(16.95,18.86) v1(16.88,12.68) v1(16.95,11.23) v1(17.02,67) v1(17,27.38) v1(17.25,56.13) v1(17.27,30) v1(17.25,20.38) v1(17.45,57.8) v1(17.43,37.53) v1(17.55,59.63) v1(17.56,39.23) v1(17.68,31.16) v1(17.7,24.45) v1(17.77,71.85) v1(17.88,8.73) v1(18,61.7) v1(18.18,39.25) v1(18.23,9.61) v1(18.43,60.43) v1(18.45,56.83) v1(18.43,18.86) v1(18.45,15.21) v1(18.52,20.38) v1(18.52,12.68) v1(18.5,11.23) v1(18.62,58.18) v1(18.6,25.78) v1(18.62,0.58) v1(18.73,33.63) v1(18.73,27.78) v1(18.77,71.85) v1(18.82,64.18) v1(18.88,69.91) v1(18.95,17.48) v1(18.98,68.41) v1(19.02,65.73) v1(18.98,62.76) v1(18.98,32) v1(19.02,7.86) v1(18.98,7.15) v1(19.15,2.13) v1(19.23,59.08) v1(19.2,1.26) v1(19.4,57.38) v1(19.45,37.38) v1(19.45,21.18) v1(19.65,22.73) v1(19.62,20.38) v1(19.75,48.28) v1(19.7,43.95) v1(19.73,15.3) v1(19.77,71.85) v1(19.77,61.48) v1(19.85,18.88) v1(20.02,67.6) v1(20.02,66.56) v1(20.25,34.45) v1(20.45,33.63) v1(20.45,10.21) v1(20.48,63.55) v1(20.5,6.43) v1(20.5,2.53) v1(20.73,59.35) v1(20.73,11.53) v1(20.77,71.85) v1(20.77,68.16) v1(20.77,67.1) v1(20.77,66.06) v1(20.77,3.73) v1(20.85,57.73) v1(21.15,24.63) v1(21.1,22.76) v1(21.1,21.18) v1(21.12,20.38) v1(21.1,18.86) v1(21.12,15.3) v1(21.48,69.78) v1(21.49,68.73) v1(21.49,67.68) v1(21.49,66.63) v1(21.48,65.56) v1(21.48,64.63) v1(21.48,63.68) v1(21.48,62.73) v1(21.48,61.73) v1(21.48,60.83) v1(21.48,59.95) v1(21.48,59.1) v1(21.73,8.3) v1(21.75,5.78) v1(21.77,71.85) v1(21.77,56.58) v1(21.93,39.45) v1(22,37.58) v1(21.98,34.45) v1(22,31.58) v1(21.98,29.91) v1(22.23,69.28) v1(22.24,68.23) v1(22.24,67.18) v1(22.24,66.13) v1(22.25,65.16) v1(22.25,64.2) v1(22.25,63.26) v1(22.25,62.26) v1(22.25,61.35) v1(22.25,60.48) v1(22.25,12.05) v1(22.25,2.13) v1(22.45,24.58) v1(22.52,22.73) v1(22.52,21.16) v1(22.48,20.38) v1(22.5,15.28) v1(22.65,14.63) v1(22.7,59.1) v1(22.77,71.85) v1(22.85,69.83) v1(22.86,68.78) v1(22.86,67.73) v1(22.86,66.68) v1(23.05,65.95) v1(23.1,64.6) v1(23.1,63.66) v1(23.1,62.7) v1(23.1,61.7) v1(23.1,60.8) v1(23.1,59.93) v1(23.15,28.41) v1(23.1,25.13) v1(23.25,29.95) v1(23.3,13.11) v1(23.52,15.48) v1(23.55,59.08) v1(23.68,33.61) v1(23.7,24.55) v1(23.82,22.73) v1(23.9,67.33) v1(24.02,65.95) v1(24.02,21.18) v1(24.12,64.6) v1(24.12,63.66) v1(24.12,62.7) v1(24.12,61.7) v1(24.12,60.8) v1(24.12,59.93) v1(24.12,34.38) v1(24.18,2.16) v1(24.35,59.08) v1(24.48,14.3) v1(24.98,65.95) v1(24.98,64.95) v1(24.98,64) v1(24.98,63.05) v1(24.98,62.05) v1(24.98,61.16) v1(24.98,60.28) v1(24.98,59.43) v1(25,58.58) v1(25.12,14.34) v1(25.18,1.05) v1(25.25,67.05) v1(25.45,21.18) v1(25.43,12.08) v1(25.4,6.98) v1(25.5,22.7) v1(25.75,60.96) v1(25.77,65.6) v1(25.77,63.66) v1(25.77,62.7) v1(25.77,61.7) v1(25.77,59.93) v1(25.77,58.91) v1(25.77,58.2) v1(25.93,64.7) v1(26.04,58.5) v1(26.2,34.38) v1(26.68,52.95) v1(26.68,51.51) v1(26.68,50.01) v1(26.68,48.41) v1(26.7,0.63) v1(26.93,22.7) v1(26.93,21.2) v1(27.65,64.7) v1(27.7,34.38) v1(27.8,67.22) v1(27.77,65.53) v1(27.77,63.58) v1(27.77,62.63) v1(27.77,61.63) v1(27.77,60.73) v1(27.77,59.85) v1(27.77,58.83) v1(27.85,66.4) v1(27.85,43.2) v1(28.05,52.93) v1(28.1,51.48) v1(28.1,49.98) v1(28.1,48.38) v1(28.1,4.68) v1(28.45,22.73) v1(28.48,60.26) v1(28.52,34.38) v1(28.65,65.95) v1(28.65,64.95) v1(28.65,64) v1(28.65,63.05) v1(28.65,62.05) v1(28.65,61.16) v1(28.6,21.16) v1(28.73,43.7) v1(28.73,43.08) v1(28.67,26.53) v1(28.88,67.35) v1(28.95,0.63) v1(29.3,12.86) v1(29.42,51.48) v1(29.42,49.98) v1(29.42,48.38) v1(29.45,65.6) v1(29.67,12.08) v1(29.77,66.67) v1(30.08,43.78) v1(30.08,43.1) v1(30.12,6.93) v1(30.23,38.73) v1(30.27,66) v1(30.3,29.43) v1(30.3,27) v1(30.3,21.08) v1(30.38,37.86) v1(30.4,34.48) v1(30.35,22.73) v1(30.4,1.8) v1(30.48,4.55) v1(30.65,69.81) v1(30.65,32.83) v1(30.57,14.96) v1(30.58,0.63) v1(30.66,68.75) v1(30.66,67.7) v1(30.66,66.66) v1(30.9,71.81) v1(31.05,51.48) v1(31.05,49.98) v1(31.05,48.38) v1(31.08,65.66) v1(31.2,21.13) v1(31.4,69.31) v1(31.41,68.25) v1(31.41,67.2) v1(31.41,66.16) v1(31.38,2.88) v1(31.62,54.38) v1(31.6,0.78) v1(31.8,22.73) v1(31.9,71.81) v1(31.9,13.46) v1(32.02,69.85) v1(32.04,68.81) v1(32.04,67.75) v1(32.04,66.7) v1(31.97,32.73) v1(32.6,54.38) v1(32.83,69.28) v1(32.84,68.23) v1(32.84,67.18) v1(32.8,51.48) v1(32.8,48.38) v1(32.77,34.43) v1(32.9,71.81) v1(33.08,2.98) v1(33.15,0.9) v1(33.45,69.83) v1(33.47,68.78) v1(33.47,67.73) v1(33.47,66.68) v1(33.5,37.86) v1(33.55,22.7) v1(33.66,27.93) v1(33.8,32.8) v1(33.9,71.81) v1(33.91,29.28) v1(34.33,68.43) v1(34.3,32.36) v1(34.4,69.73) v1(34.4,67.2) v1(34.5,37.83) v1(34.67,57.91) v1(34.7,20.98) v1(34.83,66.23) v1(34.9,71.81) v1(34.9,7.5) v1(34.9,2.21) v1(35.02,39.33) v1(35.12,34.5) v1(35.33,65.38) v1(35.33,64.31) v1(35.33,63.23) v1(35.3,44.13) v1(35.33,12.18) v1(35.65,22.73) v1(35.58,9.05) v1(35.73,69.68) v1(35.7,68.2) v1(35.75,44.55) v1(35.9,71.81) v1(35.98,65.88) v1(35.98,64.81) v1(35.98,63.73) v1(36.12,67.08) v1(36.08,19.76) v1(36.4,13.58) v1(36.4,2.11) v1(36.52,45.26) v1(36.75,37.78) v1(36.9,71.81) v1(36.88,68.83) v1(36.88,67.95) v1(36.95,69.7) v1(37,22.73) v1(36.98,14.93) v1(37.23,39.38) v1(37.33,59.42) v1(37.27,34.53) v1(37.4,0.96) v1(37.9,71.81) v1(37.88,12.05) v1(37.98,59.45) v1(38.17,68.5) v1(38.23,67.68) v1(38.27,69.81) v1(38.3,22.66) v1(38.4,61.34) v1(38.62,0.63) v1(38.75,39.36) v1(38.9,71.81) v1(39.15,6.03) v1(39.25,22.05) v1(39.38,68.78) v1(39.35,34.48) v1(39.62,27.93) v1(39.7,69.83) v1(39.67,32.68) v1(39.73,29.28) v1(39.9,71.81) v1(39.9,67.38) v1(39.92,4.28) v1(40.02,66.53) v1(40.05,46.3) v1(40.05,21.26) v1(40.08,37.88) v1(40.15,32.28) v1(40.27,65.75) v1(40.3,11.18) v1(40.35,68.25) v1(40.52,47.73) v1(40.67,69.18) v1(40.9,71.81) v1(41.12,60.01) v1(41.27,65.43) v1(41.25,34.55) v1(41.35,45.66) v1(41.52,0.61) v1(41.6,69.83) v1(41.62,9.28) v1(41.83,64.53) v1(41.9,71.81) v1(41.9,51.63) v1(41.92,51.26) v1(42.05,68.45) v1(41.95,44.98) v1(42.17,66.95) v1(42.2,59.55) v1(42.48,44.41) v1(42.52,6.11) v1(42.5,1.93) v1(42.9,71.81) v1(43.02,14.96) v1(43.12,65.45) v1(43.25,69.81) v1(43.33,54.55) v1(43.27,2.98) v1(43.42,29.41) v1(43.52,0.83) v1(43.67,4.38) v1(43.9,71.81) v1(43.85,66.98) v1(44.02,68.48) v1(44.1,64.58) v1(44.08,58.01) v1(44.15,35.5) v1(44.15,12.86) v1(44.17,34.86) v1(44.25,32.41) v1(44.6,54.45) v1(44.75,69.81) v1(44.7,52.93) v1(44.7,46.41) v1(44.7,44.6) v1(44.7,37.93) v1(44.75,28.03) v1(44.9,71.81) v1(45,57.13) v1(45.08,2.91) v1(45.3,0.83) v1(45.4,65.56) v1(45.48,18.45) v1(45.73,66.98) v1(45.9,71.81) v1(45.88,63.83) v1(45.95,68.43) v1(46.17,54.48) v1(46.2,52.85) v1(46.17,51.43) v1(46.3,34.78) v1(46.25,32.36) v1(46.42,19.86) v1(46.38,12.55) v1(46.4,9.46) v1(46.5,44.55) v1(46.45,2.16) v1(46.62,69.78) v1(46.58,30.38) v1(46.9,71.81) v1(46.9,60.38) v1(47.08,66.95) v1(47.08,15.11) v1(47.3,68.7) v1(47.35,28.28) v1(47.45,33.48) v1(47.48,26.18) v1(47.7,59.73) v1(47.75,15.88) v1(47.8,54.38) v1(47.9,71.81) v1(48.05,68.13) v1(48.15,12.05) v1(48.23,2.16) v1(48.29,30.14) v1(48.25,6.71) v1(48.38,61.35) v1(48.4,44.55) v1(48.42,34.63) v1(48.4,32.36) v1(48.9,71.81) v1(48.92,69.83) v1(48.92,66.48) v1(48.92,52.51) v1(49.02,20.13) v1(49.17,59.7) v1(49.23,1.51) v1(49.3,61.2) v1(49.3,35.38) v1(49.27,0.61) v1(49.35,57.41) v1(49.5,24.34) v1(49.62,19.58) v1(49.58,15.88) v1(49.58,13.11) v1(49.67,48.1) v1(49.9,71.81) v1(50.08,15.23) v1(50.17,67.5) v1(50.3,48.93) v1(50.25,12.4) v1(50.4,68.73) v1(50.55,29.13) v1(50.55,27.3) v1(50.62,25.33) v1(50.6,9.96) v1(50.75,57.41) v1(50.83,18.33) v1(50.77,0.61) v1(50.9,71.81) v1(50.9,61.23) v1(50.88,54.43) v1(51.02,52.55) v1(50.98,44.73) v1(51.15,5.25) v1(51.25,23.95) v1(51.42,66.25) v1(51.48,11.23) v1(51.7,69.85) v1(51.67,63.53) v1(51.83,59.7) v1(51.9,71.81) v1(51.85,67.25) v1(52.2,57.41) v1(52.55,54.08) v1(52.5,43.03) v1(52.48,0.71) v1(52.6,49.03) v1(52.67,68.41) v1(52.9,71.81) v1(52.88,7.65) v1(52.98,44.63) v1(53.12,59.7) v1(53.17,9.48) v1(53.3,48.08) v1(53.4,15.86) v1(53.5,67.88) v1(53.83,43.23) v1(53.9,71.81) v1(53.9,57.35) v1(54,50.85) v1(54,8.65) v1(53.95,6.68) v1(54.1,69.85) v1(54.1,52.6) v1(54.23,54.91) v1(54.38,14.8) v1(54.35,3.58) v1(54.4,1.88) v1(54.45,0.58) v1(54.77,34.63) v1(54.8,5.86) v1(54.9,71.81) v1(55.02,54.18) v1(54.98,50.78) v1(55.05,14.16) v1(55.1,36.25) v1(55.17,68.68) v1(55.17,7.63) v1(55.33,2.83) v1(55.48,4.93) v1(55.62,13.61) v1(55.7,40.78) v1(55.73,29.13) v1(55.9,71.81) v1(55.9,6.8) v1(55.98,26.66) v1(55.95,0.88) v1(56.08,66.63) v1(56.2,52.91) v1(56.25,63.73) v1(56.33,61.28) v1(56.6,64.85) v1(56.65,48.23) v1(56.62,12.63) v1(56.77,5.93) v1(56.9,71.81) v1(57.1,7.58) v1(57.08,3.18) v1(57.27,0.76) v1(57.45,25.23) v1(57.5,11.65) v1(57.6,48.1) v1(57.6,36.2) v1(57.65,32.23) v1(57.62,24.08) v1(57.73,4.43) v1(57.9,71.81) v1(58.02,59.45) v1(57.98,2.11) v1(58.08,61.28) v1(58.25,64.6) v1(58.48,5.66) v1(58.9,71.81) v1(58.85,8.13) v1(59.05,2.53) v1(59.12,28.55) v1(59.08,25.95) v1(59.23,46.26) v1(59.35,33.38) v1(59.52,3.8) v1(59.9,71.81) v1(59.88,61.18) v1(59.88,43.83) v1(60.02,5.66) v1(60.08,63.6) v1(60.2,41.23) v1(60.3,57.48) v1(60.3,33.38) v1(60.27,28.53) v1(60.25,8.08) v1(60.33,4.46) v1(60.45,48.76) v1(60.72,60.16) v1(60.75,58.58) v1(60.9,71.81) v1(61.4,28.25) v1(61.47,29.88) v1(61.5,16.23) v1(61.53,11.36) v1(61.62,65.23) v1(61.62,43.91) v1(61.62,40.66) v1(61.6,33.25) v1(61.6,5.61) v1(61.7,35.08) v1(61.78,42.66) v1(61.83,3.16) v1(61.9,71.81) v1(61.92,69.85) v1(62.17,55.76) v1(62.2,54.38) v1(62.22,52.95) v1(62.33,46.83) v1(62.28,22.18) v1(62.67,24.16) v1(62.78,63.63) v1(62.8,58.58) v1(62.78,29.95) v1(62.8,19.58) v1(62.83,4.43) v1(62.9,71.81) v1(62.9,37.11) v1(62.92,17.78) v1(62.97,66.95) v1(63.05,32.58) v1(63.08,5.66) v1(63.47,45.7) v1(63.55,3.13) v1(63.75,53.76) v1(63.78,66.31) v1(63.78,55.53) v1(63.9,71.81) v1(63.88,34.86) v1(63.95,25.23) v1(63.97,10.13) v1(64.45,69.85) v1(64.5,66.83) v1(64.6,4.5) v1(64.65,60.28) v1(64.9,71.81) v1(64.92,57.8) v1(64.95,63.78) v1(64.97,41.16) v1(65.03,36.16) v1(65.1,38.63) v1(65.17,53.88) v1(65.33,10.73) v1(65.3,3.25) v1(65.38,8.21) v1(65.6,18.41) v1(65.62,5.71) v1(65.9,71.81) v1(65.9,20.91) v1(65.97,15.83) v1(66.08,64.38) v1(66.12,62.66) v1(66.08,51.41) v1(66.4,53.88) v1(66.55,10.68) v1(66.58,8.13) v1(66.85,69.85) v1(66.83,57.3) v1(66.78,25.93) v1(66.9,71.81) v1(66.95,3.18) v1(67.22,60.55) v1(67.45,63.28) v1(67.9,71.81) v1(67.97,58.28) v1(67.97,22.36) v1(67.95,4.98) v1(68.3,54.53) v1(68.3,8.3) v1(68.3,7.4) v1(68.4,9.68) v1(68.72,15.33) v1(68.7,3.23) v1(68.9,71.81) v1(69.2,48.01) v1(69.25,57.35) v1(69.35,30.91) v1(69.35,12.08) v1(69.42,69.88) v1(69.47,4.98) v1(69.67,53.26) v1(69.7,9.71) v1(69.78,29.61) v1(69.9,71.81) v1(69.9,36.78) v1(69.92,33.93) v1(69.92,14.58) v1(70.05,22.58) v1(70.08,40.78) v1(70.15,25.05) v1(70.35,3.18) v1(70.85,48.33) v1(70.78,43.7) v1(70.8,39.55) v1(70.78,26.66) v1(70.9,71.81) v1(70.92,32.61) v1(71,33.95) v1(71.12,6.88) v1(71.3,4.86) v1(71.9,71.81) v1(72.12,3.25) v1(72.22,69.88) v1(72.3,33.93) v1(72.42,49.98) v1(72.47,55.45) v1(72.85,17.25) v1(72.9,71.81) v1(72.97,63.33) v1(72.97,47.16) v1(73.12,43.68) v1(73.2,4.86) v1(73.33,40.13) v1(73.3,12.13) v1(73.25,7) v1(73.58,9.88) v1(73.67,42.28) v1(73.72,38.86) v1(73.78,41.03) v1(73.85,34) v1(73.9,71.81) v1(73.92,30.05) v1(73.9,26.41) v1(74.03,64.48) v1(74,21.93) v1(74.2,14.58) v1(74.28,23.98) v1(74.38,62.55) v1(74.47,3.23) v1(74.67,69.85) v1(74.9,71.81) v1(74.92,12.73) v1(75.3,29.5) v1(75.3,28.05) v1(75.35,11.65) v1(75.5,63.51) v1(75.5,52.8) v1(75.45,46.58) v1(75.45,31.38) v1(75.45,5) v1(75.67,9.76) v1(75.85,57.66) v1(75.83,3.25) v1(75.9,71.81) v1(75.97,49.98) v1(75.95,16.8) v1(75.95,7.5) v1(76.1,52.16) v1(76.12,22.38) v1(76.3,68.85) v1(76.33,24.68) v1(76.72,4.18) v1(76.9,71.81) v1(77.05,71.08) v1(76.97,62.88) v1(77,38.7) v1(77,36.93) v1(77.1,70.08) v1(77.1,69.08) v1(77.1,68.08) v1(77.1,67.08) v1(77.1,66.08) v1(77.1,65.08) v1(77.1,64.08) v1(77.1,62.08) v1(77.1,61.08) v1(77.1,60.08) v1(77.1,59.08) v1(77.1,58.08) v1(77.1,57.08) v1(77.1,56.08) v1(77.1,55.08) v1(77.1,54.08) v1(77.1,53.08) v1(77.1,52.08) v1(77.1,51.08) v1(77.1,50.08) v1(77.1,49.08) v1(77.1,48.08) v1(77.1,47.08) v1(77.1,46.35) v1(77.1,44.8) v1(77.1,44.08) v1(77.1,43.08) v1(77.1,42.08) v1(77.1,40.08) v1(77.1,38.08) v1(77.1,36.08) v1(77.1,35.08) v1(77.1,32.08) v1(77.1,31.08) v1(77.1,30.08) v1(77.1,27.08) v1(77.1,24.08) v1(77.1,23.08) v1(77.08,22.2) v1(77.1,20.08) v1(77.08,19.23) v1(77.1,17.08) v1(77.1,16.08) v1(77.1,15.08) v1(77.12,12.83) v1(77.1,12.08) v1(77.1,9.08) v1(77.1,8.08) v1(77.1,7.08) v1(77.6,5.03) v1(77.95,71.08) v1(77.95,70.08) v1(77.95,69.08) v1(77.95,68.08) v1(77.95,67.08) v1(77.95,66.08) v1(77.95,65.08) v1(77.95,64.08) v1(77.95,63.08) v1(77.95,62.08) v1(77.95,61.08) v1(77.95,60.08) v1(77.95,59.08) v1(77.95,58.08) v1(77.95,57.08) v1(77.95,56.08) v1(77.95,55.08) v1(77.95,54.08) v1(77.95,53.08) v1(77.95,52.08) v1(77.95,51.08) v1(77.95,50.08) v1(77.95,49.08) v1(77.95,48.08) v1(77.95,47.08) v1(77.95,46.08) v1(77.95,45.08) v1(77.95,44.08) v1(77.95,43.08) v1(77.95,42.08) v1(77.95,41.08) v1(77.95,40.08) v1(77.95,39.08) v1(77.95,38.08) v1(77.95,37.08) v1(77.95,36.08) v1(77.95,35.08) v1(77.95,34.08) v1(77.95,33.08) v1(77.95,32.08) v1(77.95,31.08) v1(77.95,30.08) v1(77.95,29.08) v1(77.95,28.08) v1(77.95,27.08) v1(77.95,26.08) v1(77.95,25.08) v1(77.95,24.08) v1(77.95,23.08) v1(77.95,22.08) v1(77.95,21.08) v1(77.95,20.08) v1(77.95,19.08) v1(77.95,18.08) v1(77.95,17.08) v1(77.95,16.08) v1(77.95,15.08) v1(77.95,14.08) v1(77.95,13.08) v1(77.95,12.08) v1(77.95,11.08) v1(77.95,10.08) v1(77.95,9.08) v1(77.95,8.08) v1(77.95,7.08) v1(77.95,6.08) v2(33.5,58.51)
VBAT_ADJ: length 17.9
  TOP w0.5: U7.4 U7.2 71.9,45.28 R33.2 71.97,45.76 C44.1 70.55,45.76 70.05,46.26 70.05,48.27 v1(68.35,49.97)
  BOTTOM w0.5: v1(68.35,49.97) 65.97,49.97 J9.6
VBUS: length 144
  TOP w0.5: v1(11.75,10.33) 11.47,10.05 R9.1 ; C43.1 69,45.66 v1(69,44.8) 69.6,44.2 U7.3
  POWER w0.5: v1(9.75,51.73) 9,50.98 3.35,50.98 2.51,51.82 v1(2.51,52.85) ; v1(21.1,25.88) 44.83,25.88 50.48,20.23 57.42,20.23 68.53,31.34 68.53,44.33 v1(69,44.8) 68.45,45.35 68.45,48.68 67.6,49.53 67.6,51.13 67.62,51.16 v1(67.62,55.15) ; v1(16.22,21) 11.75,16.53 v1(11.75,10.33)
  BOTTOM w0.5: J9.2 v1(67.62,55.15) ; v1(9.75,51.73) 9.75,51.55 21.1,40.2 v1(21.1,25.88) v1(16.22,21) ; R38.1 v1(2.51,52.85)
VDDO1P8: length 48.1
  BOTTOM w0.5: 2.1,34.98 4.33,32.75 4.33,31.8 2.42,29.89 2.21,29.89 ; 2.1,34.98 1.67,34.98 ; 2.1,34.98 4.03,36.9 4.03,40.78 2.21,42.59 J8.5 ; 2.21,29.89 4.22,27.89 4.22,26.85 2.18,24.81 ; 2.21,29.89 1.67,29.89 ; 2.18,24.81 2.46,24.81 4.74,22.53 4.74,22.03 4.72,22.02 4.72,22.01 4.34,21.63 4.34,21.63 2.45,19.73 ; 2.18,24.81 1.67,24.81 ; 1.67,14.66 2.2,14.66 ; 2.2,14.66 2.5,14.66 4.53,12.63 4.53,11.9 2.2,9.57 1.67,9.57 ; 2.2,14.66 4.51,16.96 4.51,17.67 2.45,19.73 ; 1.67,19.73 2.45,19.73
VDDO3: length 44.7
  BOTTOM w0.5: J8.3 2.22,45.13 4.68,42.68 4.68,39.1 6.26,37.52 ; 7.45,27.36 7.4,27.36 6.3,28.45 6.3,31.36 7.38,32.44 7.42,32.44 ; 7.45,27.36 J8.18 ; 7.45,27.36 6.28,26.18 6.28,23.23 7.23,22.27 ; 6.25,36.93 6.25,37.5 6.26,37.52 ; 6.25,36.93 6.25,33.61 7.42,32.44 ; 6.25,36.93 6.84,37.52 ; 7.42,32.44 J8.14 ; 6.26,37.52 6.84,37.52 ; 7.37,17.2 7.34,17.2 6.38,18.16 6.38,21.42 7.23,22.27 ; 7.37,17.2 6.38,16.2 6.38,13.28 7.54,12.12 J8.30 ; 7.37,17.2 J8.26 ; 6.84,37.52 J8.10 ; 7.23,22.27 J8.22
AIN_LINEIN: length 22.1
  TOP w0.2: 65.88,6.9 65.3,6.9 63.47,5.08 56.73,5.08 48.55,13.25 C40.2
AIN_MIC: length 22.9
  TOP w0.2: v1(49.9,11.18) 46.35,14.73 C38.2 ; v1(63.53,9.45) 65.88,9.45
  BOTTOM w0.2: v1(49.9,11.18) 50.42,10.65 62.31,10.65 v1(63.53,9.45)
BEVK_SWS: length 10.1
  TOP w0.2: R37.2 12.77,55.1 R11.2 11.28,54.26 7.51,54.26 7.5,54.24 6.55,54.24 6.54,54.26 5.62,54.26 4.49,55.4
DM: length 6.1
  TOP w0.2: J2.B7 15,5.53 15.2,5.33 15.8,5.33 16,5.53 J2.A7 16,8.36 D14.1 16.32,8.73 R6.1
DMICCK1: length 47.7
  TOP w0.2: J7.29 10.14,12.1 11.72,13.68 24.68,13.68 v1(24.73,13.63) ; v1(48.4,24.34) R27.2 48.4,25.66 U5.4
  BOTTOM w0.2: v1(48.4,24.34) 47.3,23.23 35.44,23.23 25.84,13.63 v1(24.73,13.63)
DMICCK2: length 27.9
  TOP w0.2: J7.31 8.1,9.56 11.72,13.18 v1(20.38,13.18) ; v1(20.38,23.05) R28.2 20.38,26.17 20.38,26.17 U6.4
  BOTTOM w0.2: v1(20.38,23.05) v1(20.38,13.18)
DMICDAT: length 61
  TOP w0.2: v1(21.82,14.66) 21.81,14.64 19.25,14.64 ; 18.95,14.92 18.68,14.64 ; 18.95,14.92 C122.1 ; 18.95,14.92 18.95,14.64 18.95,14.64 ; 18.95,14.92 18.97,14.92 19.25,14.64 ; 18.68,14.64 J7.27 ; 18.68,14.64 18.95,14.64 ; v1(48.05,27.89) U5.5 ; v1(43.83,23.78) 42.22,23.78 41.92,24.08 25.73,24.08 22.45,27.36 v1(21.82,27.36) 21.82,27.36 U6.5 ; 18.95,14.64 19.25,14.64
  BOTTOM w0.2: v1(48.05,27.89) 47.94,27.89 v1(43.83,23.78) ; v1(21.82,27.36) v1(21.82,14.66)
DP: length 5.6
  TOP w0.2: J2.A6 v1(15.5,7.4) 15.5,8.63 D13.1 R4.1 ; v1(16.5,7.4) J2.B6
  BOTTOM w0.2: v1(15.5,7.4) v1(16.5,7.4)
EXT_3V3: length 121.6
  TOP w0.4: 15.18,55.76 C34.1 15.18,53.88 15.15,53.85 v1(15.15,53.73)
  POWER w0.5: v1(22.35,33.58) 22.38,33.55 22.38,32.5 24.05,30.83 40.83,30.83 50.77,20.88 57.15,20.88 67.8,31.53 67.8,48.41 v1(63.7,52.51) ; v1(15.15,53.73) 15.15,57.53 8.12,64.56 8.03,64.56 7.03,65.56
  BOTTOM w0.5: v1(15.15,53.73) 15.15,51.77 23.02,43.9 23.02,34.25 v1(22.35,33.58) ; v1(63.7,52.51) 65.78,52.51 J9.4
LED_B: length 26.7
  TOP w0.2: R20.1 43.8,30.66 v1(43.9,30.66) ; v1(63.72,29.98) 65.66,29.98 J6.21
  BOTTOM w0.2: v1(63.72,29.98) 62.67,31.03 44.27,31.03 v1(43.9,30.66)
LED_G: length 26.2
  TOP w0.2: J6.17 65.34,34.84 64.42,33.93 v1(64.15,33.93) ; R22.1 41,31.66 v1(42.27,32.93)
  BOTTOM w0.2: v1(42.27,32.93) 58.01,32.93 59.01,33.93 v1(64.15,33.93)
LED_R: length 32.7
  TOP w0.2: v1(61.2,31.53) 61.2,31.5 61.33,31.38 64.4,31.38 65.33,32.3 J6.19 ; R19.1 35.17,28.03 36.95,29.8 41.75,29.8 v1(42.92,30.98)
  BOTTOM w0.2: v1(42.92,30.98) 43.33,31.38 61.05,31.38 v1(61.2,31.53)
LED_VBAT: length 56
  TOP w0.5: v1(44.61,17.33) 44.61,24 43.62,24.98 26.23,24.98 24.18,27.03 R13.1 R12.1 R15.1 R14.1
  BOTTOM w0.5: v1(44.61,17.33) 44.62,17.33 44.65,17.36 53.98,17.36 55.17,18.54 64.19,18.54 65.24,19.59 J9.30
LED_W: length 33.2
  TOP w0.2: R21.1 37.23,33.88 43.2,33.88 v1(43.6,34.28) ; v1(61.25,35.73) 63.65,35.73 65.31,37.39 J6.15
  BOTTOM w0.2: v1(43.6,34.28) 43.85,34.03 56.39,34.03 58.09,35.73 v1(61.25,35.73)
LEVEL_SHIFT: length 58.1
  TOP w0.4: v1(13.38,53.66) 14.07,53.66 14.52,54.1 U3.5 14.52,56.43 15.18,57.08 C35.1
  POWER w0.4: v1(13.38,53.66) 2.47,42.76 2.47,8.78 v1(2,8.3)
  BOTTOM w0.4: 1.67,7.04 1.67,7.98 v1(2,8.3)
MICBIAS: length 20.3
  TOP w0.2: J6.35 65.3,11.98 64.25,13.03 58.38,13.03 v1(52.43,18.98) ; R18.1 v1(49.42,18.95)
  BOTTOM w0.2: v1(49.42,18.95) 52.4,18.95 52.4,18.98 v1(52.43,18.98)
TL_ANT: length 2.5
  TOP w0.2: U8.64 26.77,57.05
  TOP w0.5: C1.1 D7.2 26.77,57.05
TL_AVDD0P94: length 38.2
  TOP w0.2: U8.42 35.95,54.45 36,54.51
  TOP w0.3: 36,54.51 36.4,54.91 36.8,54.91 v1(36.8,54.91)
  POWER w0.5: v1(58,37.53) 58,44.71 52.88,49.83 45.35,49.83 v1(43.98,51.2)
  BOTTOM w0.3: C28.1 38.2,55.33 41.19,55.33 42.29,54.23
  BOTTOM w0.4: C28.1 37.4,54.78 37.27,54.91 36.8,54.91 v1(36.8,54.91)
  BOTTOM w0.5: v1(58,37.53) 59.41,37.53 59.58,37.37 ; v1(43.98,51.2) 44.02,51.26 44.02,52.5 42.29,54.23
TL_AVDD3: length 75.3
  TOP w0.2: U8.49 v1(32.02,55.2)
  POWER w0.5: v1(36.79,61.64) 37.79,62.63 37.8,62.63 37.83,62.66 45.83,62.66 48.08,60.41 54.27,60.41 58.58,56.1 58.58,53.8 67.15,45.23 67.15,31.8 v1(61.69,26.34)
  BOTTOM w0.35: v1(32.02,55.2) 32.02,55.6 C15.1
  BOTTOM w0.5: v1(61.69,26.34) 60.02,24.67 59.58,24.67 ; v1(36.79,61.64) 36.8,61.64 36.8,61.63 34.43,59.26 31.92,59.26 31.42,58.76 31.42,57.45 30.92,56.95 C15.1
TL_DM: length 11.6
  TOP w0.2: J7.33 8.63,7.02 10.15,8.54 10.15,10.11 11.53,11.48 15.6,11.48 16.32,10.76 R6.2
TL_DP: length 12.5
  TOP w0.2: R4.2 14.9,11.13 11.67,11.13 10.5,9.96 10.5,8.4 9.57,7.47 9.57,5.5 8.55,4.48 7.97,4.48
TL_DVDD0P94: length 41.8
  TOP w0.2: 36.35,54.16 36.3,54.1 U8.41
  TOP w0.3: 36.35,54.16 36.5,54.3 v1(36.95,54.3)
  POWER w0.5: v1(57.8,34.73) 58.85,35.78 58.85,44.88 53.05,50.68 45.58,50.68 44.08,52.18 v1(43.38,52.18)
  BOTTOM w0.3: C27.1 36.75,54.03 36.95,54.23 v1(36.95,54.3)
  BOTTOM w0.5: v1(43.38,52.18) 43.23,52.33 37.7,52.33 36.75,53.28 C27.1 ; 59.58,34.83 59.48,34.73 v1(57.8,34.73)
TL_FLASH: length 92.5
  TOP w0.2: 13.27,69.28 13.43,69.13 v1(13.43,68.45) ; 13.27,69.28 SW2.1 ; 13.27,69.28 SW2.2
  TOP w0.5: U2.8 C33.1 27.8,38.24 28.07,37.97 ; 28.07,37.88 28.85,37.11 ; 28.07,37.88 28.07,37.11 ; 28.07,37.88 28.07,37.97 ; 28.85,37.11 34.82,37.11 v1(36.32,38.61) ; 28.85,37.11 28.82,37.07 28.11,37.07 28.07,37.11 ; 27.21,37.11 26.99,36.89 25.16,36.89 23.65,38.39 23.65,42.26 R3.1 23.1,42.91 22.43,43.58 v1(22.38,43.58) ; 27.21,37.11 28.07,37.97 ; 27.21,37.11 27.26,37.05 28.02,37.05 28.07,37.11
  POWER w0.5: v1(54.95,41.11) 52.79,41.11 49.99,38.3 48.08,38.3 47.78,38.61 v1(36.32,38.61)
  BOTTOM w0.5: v1(13.43,68.45) 13.43,62.73 11.78,61.08 11.78,54.23 22.38,43.63 v1(22.38,43.58) ; 59.58,42.45 59.05,42.45 58.92,42.33 56.17,42.33 v1(54.95,41.11)
TL_IR: length 53.4
  TOP w0.2: U8.45 33.42,56.4 arc(33.44,56.47) 33.48,56.54 33.6,56.66 arc(33.71,56.73) 33.84,56.76 36.09,56.76 36.74,57.41
  TOP w0.3: J6.9 65.35,45.01 62.9,47.45 62.9,56.88 v1(63.17,57.16)
  TOP w0.35: 36.74,57.41 v1(41.08,57.41)
  BOTTOM w0.4: 47.91,62.58 60.38,62.58 62.1,60.85 62.1,57.55 62.5,57.16 v1(63.17,57.16) ; 47.91,62.58 47.08,62.58 ; 47.91,62.58 47.51,62.98 47.51,63.01 ; 47.08,62.58 46.62,62.58 41.45,57.41 v1(41.08,57.41) ; 47.08,62.58 47.51,63.01 ; 47.51,63.01 D5.C
TL_IR_EX_DIOD: length 49.1
  TOP w0.2: 35.27,55.3 35.12,55.16 34.3,55.16
  TOP w0.3: v1(61.47,57.1) 61.47,46.48 60,45.01 59.58,45.01 ; v1(41.91,57.02) 41.75,56.85 36.83,56.85 35.27,55.3
  TOP w0.4: v1(55.73,61.95) 54.65,63.03 D6.C
  BOTTOM w0.4: v1(41.91,57.02) 46.85,61.95 v1(55.73,61.95) 60.2,61.95 61.47,60.68 v1(61.47,57.1)
TL_KEY1: length 54.8
  TOP w0.2: 73.33,33.29 SW4.1 67.85,33.89 67.85,53.83 66.52,55.16 65.88,55.16 ; 73.33,33.29 v1(73.33,33.28) ; 73.33,33.29 SW4.2 ; 73.31,18.22 SW3.2 ; 73.31,18.22 v1(73.33,18.23) ; 73.31,18.22 SW3.1
  BOTTOM w0.2: v1(73.33,33.28) v1(73.33,18.23)
TL_KEY2: length 59.5
  TOP w0.2: 70.92,10.69 v1(70.92,10.68) ; 70.92,10.69 SW5.2 ; 70.92,10.69 SW5.1 ; SW6.2 75.63,25.73 75.61,25.76 v1(70.92,25.76) 69.44,25.76 69.42,25.73 SW6.1 68.45,27.19 67.45,28.19 67.45,51.05 J6.3
  BOTTOM w0.2: v1(70.92,10.68) v1(70.92,25.76)
TL_KEY3: length 63.5
  TOP w0.2: SW3.3 72.22,13.72 v1(72.22,13.73) 72.22,13.72 SW3.4 ; 72.2,6.19 SW5.3 ; 72.2,6.19 SW5.4 ; 72.2,6.19 v1(72.22,6.21) ; v1(65.88,48.91) J6.5
  BOTTOM w0.2: v1(65.88,48.91) 66.8,48.91 71.8,43.91 71.8,14.16 v1(72.22,13.73) v1(72.22,6.21)
TL_KEY4: length 43.9
  TOP w0.2: SW6.3 v1(72.42,21.23) SW6.4 ; v1(66.95,46.49) 66.96,46.49 66.85,46.6 66.81,46.6 J6.7 ; SW4.4 v1(72.55,28.79) SW4.3 v1(68.45,29.73)
  BOTTOM w0.2: v1(66.95,46.49) 66.96,46.49 68.45,45.01 v1(68.45,29.73) ; v1(72.55,28.79) 72.55,21.36 v1(72.42,21.23)
TL_PA0: length 38.4
  TOP w0.2: 1.67,19.72 2.22,19.72 4.7,22.2 4.7,23.73 7.15,26.18 v1(11.55,26.18) ; v1(11.95,31.68) 13.65,33.38 13.65,39.11 16.27,41.73 16.27,43.73 19.91,47.37 R47.1
  BOTTOM w0.2: v1(11.55,26.18) 11.55,31.28 v1(11.95,31.68)
TL_PA0_SDMP0: length 25.5
  TOP w0.2: TP8.1 31.35,20.43 30.35,19.43 L17.1 28.55,19.43 27.62,20.36 23.6,20.36 23.07,19.83 8.09,19.83 J7.23
TL_PA1: length 41
  TOP w0.2: R46.1 19.52,46.48 16.62,43.59 16.62,41.59 14,38.96 14,32.83 12.3,31.13 v1(12.3,30.91) ; 1.67,17.18 2.28,17.18 3.15,18.05 3.15,19.64 6.67,23.16 12.12,23.16 v1(12.15,23.13)
  BOTTOM w0.2: v1(12.15,23.13) 12.25,23.23 12.25,30.86 v1(12.3,30.91)
TL_PA1_SDMN0: length 21
  TOP w0.2: 24.75,19.43 23.57,18.26 TP9.1 ; 24.75,19.43 L18.1 ; 24.75,19.43 10.75,19.43 8.5,17.18 J7.25
TL_PA2: length 48.9
  TOP w0.2: 1.67,14.64 2.16,14.64 4.88,17.36 4.88,18.98 6.8,20.91 11.32,20.91 12.95,22.53 v1(12.95,23.93) ; U8.1 26.07,46.45 25.55,45.93 19.46,45.93 16.98,43.44 16.98,41.44 14.35,38.81 14.35,32.41 12.95,31.01 v1(12.95,30.11)
  BOTTOM w0.2: v1(12.95,30.11) v1(12.95,23.93)
TL_PA3: length 52.8
  TOP w0.2: v1(13.65,31) 14.7,32.05 14.7,38.67 17.32,41.3 17.32,43.3 19.61,45.58 25.7,45.58 26.43,46.31 U8.2 ; v1(13.62,17.18) 13.62,16.88 12.82,16.08 6.2,16.08 2.22,12.1 1.67,12.1
  BOTTOM w0.2: v1(13.65,31) 13.62,30.98 v1(13.62,17.18)
TL_PA4: length 55.7
  TOP w0.2: v1(14.38,16.68) 14,16.68 13.05,15.73 6.35,15.73 3.15,12.54 3.15,10.58 2.15,9.58 1.7,9.58 1.67,9.56 ; v1(14.38,30.25) 15.07,30.95 15.07,38.53 17.68,41.13 17.68,43.15 19.75,45.23 25.84,45.23 26.77,46.16 U8.3
  BOTTOM w0.2: v1(14.38,16.68) v1(14.38,30.25)
TL_PA5_DM: length 60.5
  TOP w0.2: 1.67,7.02 5.12,7.02 6.58,8.49 9.11,8.49 9.45,8.83 9.45,10.41 11.21,12.18 19.12,12.18 19.34,12.4 19.35,12.4 19.35,12.41 v1(19.35,12.41) ; U8.10 v1(29.23,38.91)
  BOTTOM w0.2: v1(19.35,12.41) 19.35,12.41 19.35,12.4 19.52,12.58 21.38,12.58 29.23,20.43 v1(29.23,38.91)
TL_PA6_DP: length 62.3
  TOP w0.2: v1(19.38,11.73) 19.27,11.84 19.26,11.83 11.36,11.83 9.8,10.27 9.8,8.69 9.25,8.14 6.88,8.14 5.38,6.63 4.35,6.63 2.2,4.48 1.67,4.48 ; U8.11 29.58,39.75 v1(29.73,39.61)
  BOTTOM w0.2: v1(29.73,39.61) 29.73,20.38 21.43,12.08 19.73,12.08 v1(19.38,11.73)
